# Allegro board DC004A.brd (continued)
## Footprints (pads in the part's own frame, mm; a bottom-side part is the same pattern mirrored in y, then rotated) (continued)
DBV5
  rect 1.27x0.508 smd: 1(-1.1,0.95) 2(-1.1,0) 3(-1.1,-0.95) 4(1.1,-0.95) 5(1.1,0.95)
DIODE_MBRB2515L
  rect 3.048x1.016 smd: 1(5.652,-2.54) 3(5.652,2.54)
  round 0.013 smd: 2(5.652,0)
  rect 8.382x10.668 smd: 4(-5.652,0)
DIODE_SM_1N4148W
  rect 0.889x0.94 smd: 1(-1.575,0) 2(1.575,0)
DUAL_FLATPACK_TPS7H1101-SP
  rect 1.422x0.551 smd: 1(-7.303,4.445) 2(-7.303,3.175) 3(-7.303,1.905) 4(-7.303,0.635) 5(-7.303,-0.635) 6(-7.303,-1.905) 7(-7.303,-3.175) 8(-7.303,-4.445) 9(7.303,-4.445) 10(7.303,-3.175) 11(7.303,-1.905) 12(7.303,-0.635) 13(7.303,0.635) 14(7.303,1.905) 15(7.303,3.175) 16(7.303,4.445)
  rect 6.223x8.89 smd: 17(0,0)
HDR_THVT_1X2_100_M
  rect 1.473x1.473 hole 0.965: 1(0,0)
  round 1.473 hole 0.965: 2(0,-2.54)
HDR_THVT_1X3_100_M
  rect 1.575x1.575 hole 1.016: 1(0,0)
  round 1.575 hole 1.016: 2(0,-2.54) 3(0,-5.08)
HDR_THVT_1X4_100_M
  rect 1.473x1.473 hole 0.965: 1(0,0)
  round 1.473 hole 0.965: 2(0,-2.54) 3(0,-5.08) 4(0,-7.62)
HDR_THVT_2X4_100_M
  rect 1.473x1.473 hole 0.965: 1(0,0)
  round 1.473 hole 0.965: 2(2.54,0) 3(0,-2.54) 4(2.54,-2.54) 5(0,-5.08) 6(2.54,-5.08) 7(0,-7.62) 8(2.54,-7.62)
IND_0603
  rect 0.635x1.016 smd: 1(-0.635,0) 2(0.635,0)
IND_SM_6P7MMX6P7MM
  rect 2.5x2.4 smd: 1(-3.1,0) 2(3.1,0)
JUMPER_SMD_3POS_0402
  rect 0.508x0.508 smd: 1(1.016,0) 2(0,0) 3(-1.016,0)
JUMPER_SMD_3POS_0805
  rect 1.3x1.3 smd: 1(-2.032,0) 2(0,0) 3(2.032,0)
LED_0805
  rect 1.422x1.524 smd: 1(-1.143,0) 2(1.143,0)
MFG125_PLATED
  round 3.556 hole 3.175: 1(0,0)
MSOP_8_118X118_0P65MM
  rect 1.45x0.46 smd: 1(-2.2,0.975) 2(-2.2,0.325) 3(-2.2,-0.325) 4(-2.2,-0.975) 5(2.2,-0.975) 6(2.2,-0.325) 7(2.2,0.325) 8(2.2,0.975)
PROBE_POINT_30PAD
  round 0.762 smd: 1(0,0)
QFN40_RTA_RTB_RHA
  custom 0.076x0.076 smd: 1(-3.025,2.25) 2(-3.025,1.75) 3(-3.025,1.25) 4(-3.025,0.75) 5(-3.025,0.25) 6(-3.025,-0.25) 7(-3.025,-0.75) 8(-3.025,-1.25) 9(-3.025,-1.75) 10(-3.025,-2.25) 11(-2.25,-3.025) 12(-1.75,-3.025) 13(-1.25,-3.025) 14(-0.75,-3.025) 15(-0.25,-3.025) 16(0.25,-3.025) 17(0.75,-3.025) 18(1.25,-3.025) 19(1.75,-3.025) 20(2.25,-3.025) 21(3.025,-2.25) 22(3.025,-1.75) 23(3.025,-1.25) 24(3.025,-0.75) 25(3.025,-0.25) 26(3.025,0.25) 27(3.025,0.75) 28(3.025,1.25) 29(3.025,1.75) 30(3.025,2.25) 31(2.25,3.025) 32(1.75,3.025) 33(1.25,3.025) 34(0.75,3.025) 35(0.25,3.025) 36(-0.25,3.025) 37(-0.75,3.025) 38(-1.25,3.025) 39(-1.75,3.025) 40(-2.25,3.025)
  rect 4.572x4.572 smd: 41(0,0)
QFN_10_83X83_RUN
  rect 0.95x0.28 smd: 1(-0.895,0.75) 2(-0.895,0.25) 3(-0.895,-0.25) 4(-0.895,-0.75) 6(0.895,-0.75) 7(0.895,-0.25) 8(0.895,0.25) 9(0.895,0.75)
  rect 0.28x0.95 smd: 5(0,-0.895) 10(0,0.895)
QFN_64_0P50MM_RGC_FT2232HQ
  custom 0.076x0.076 smd: 1(-4.58,3.753) 2(-4.58,3.252) 3(-4.58,2.752) 4(-4.58,2.252) 5(-4.58,1.751) 6(-4.58,1.251) 7(-4.58,0.751) 8(-4.58,0.25) 9(-4.58,-0.25) 10(-4.58,-0.751) 11(-4.58,-1.251) 12(-4.58,-1.751) 13(-4.58,-2.252) 14(-4.58,-2.752) 15(-4.58,-3.252) 16(-4.58,-3.753) 17(-3.753,-4.58) 18(-3.252,-4.58) 19(-2.752,-4.58) 20(-2.252,-4.58) 21(-1.751,-4.58) 22(-1.251,-4.58) 23(-0.751,-4.58) 24(-0.25,-4.58) 25(0.25,-4.58) 26(0.751,-4.58) 27(1.251,-4.58) 28(1.751,-4.58) 29(2.252,-4.58) 30(2.752,-4.58) 31(3.252,-4.58) 32(3.753,-4.58) 33(4.58,-3.753) 34(4.58,-3.252) 35(4.58,-2.752) 36(4.58,-2.252) 37(4.58,-1.751) 38(4.58,-1.251) 39(4.58,-0.751) 40(4.58,-0.25) 41(4.58,0.25) 42(4.58,0.751) 43(4.58,1.251) 44(4.58,1.751) 45(4.58,2.252) 46(4.58,2.752) 47(4.58,3.252) 48(4.58,3.753) 49(3.753,4.58) 50(3.252,4.58) 51(2.752,4.58) 52(2.252,4.58) 53(1.751,4.58) 54(1.251,4.58) 55(0.751,4.58) 56(0.25,4.58) 57(-0.25,4.58) 58(-0.751,4.58) 59(-1.251,4.58) 60(-1.751,4.58) 61(-2.252,4.58) 62(-2.752,4.58) 63(-3.252,4.58) 64(-3.753,4.58)
  rect 4.318x4.318 smd: 65(0,0)
SJP2_JUMPER_0402
  rect 0.762x1.27 smd: 1(-0.521,0) 2(0.521,0)
SMA_SMEL_373X312
  rect 0.635x5.08 smd: 1(0,-2.54)
  rect 2.286x5.08 smd: 2(-4.445,-2.54) 3(4.445,-2.54) 4(-4.445,-2.54) 5(4.445,-2.54)
SMA_THVT_312X312
  round 2.337 hole 1.575: 1(0,0)
  round 2.464 hole 1.702: 2(-2.54,2.54) 3(2.54,2.54) 4(2.54,-2.54) 5(-2.54,-2.54)
SMA_THVT_SMT_250X250
  round 0.787 smd: 1(0,0)
  round 1.829 hole 1.499: 2(-2.54,-2.54) 3(2.54,-2.54) 4(2.54,2.54) 5(-2.54,2.54)
SMD_JUMPER_L_0402
  rect 0.508x0.508 smd: 1(-0.508,0) 2(0.508,0) 3(0.508,1.016)
SMP_B120
  rect 0.508x1.321 smd: 1(0,-3.1)
  custom 1.3x1.3 smd: 2(0,0)
SO_8_207X207_50
  rect 1.702x0.66 smd: 1(-3.645,1.905) 2(-3.645,0.635) 3(-3.645,-0.635) 4(-3.645,-1.905) 5(3.645,-1.905) 6(3.645,-0.635) 7(3.645,0.635) 8(3.645,1.905)
SOIC_8_197X157_50
  rect 2.159x0.61 smd: 1(-2.44,1.905) 2(-2.44,0.635) 3(-2.44,-0.635) 4(-2.44,-1.905) 5(2.44,-1.905) 6(2.44,-0.635) 7(2.44,0.635) 8(2.44,1.905)
SON_Q5B_8
  rect 1.372x0.711 smd: 1(-2.767,1.905) 2(-2.767,0.635) 3(-2.767,-0.635) 4(-2.767,-1.905) 5(2.767,-1.905) 6(2.767,-0.635) 7(2.767,0.635) 8(2.767,1.905)
SOT_5_120X69_37
  rect 0.61x1.524 smd: 1(-0.95,-1.75) 2(0,-1.75) 3(0.95,-1.75) 4(0.95,1.75) 5(-0.95,1.75)
SOT_5_120X69_57
  rect 0.61x1.524 smd: 1(-0.95,-1.35) 2(0,-1.35) 3(0.95,-1.35) 4(0.95,1.35) 5(-0.95,1.35)
TANT_B
  rect 2.032x2.286 smd: 1(-1.524,0) 2(1.524,0)
TANT_D
  rect 2.108x2.591 smd: 1(-2.896,0) 2(2.896,0)
TANT_X
  rect 2.108x2.591 smd: 1(-2.896,0) 2(2.896,0)
TFMR_5_150X150_50
  rect 1.651x0.762 smd: 1(1.587,1.27) 2(1.587,0) 3(1.587,-1.27) 4(-1.587,-1.27) 6(-1.587,1.27)
TP_THVT_100_RND
  round 2.54 hole 1.016: 1(0,0)
TP_THVT_125_RND_063D
  round 2.362 hole 1.6: 1(0,0)
TSSOP_16_201X177_26
  rect 1.6x0.35 smd: 1(-2.825,2.275) 2(-2.825,1.625) 3(-2.825,0.975) 4(-2.825,0.325) 5(-2.825,-0.325) 6(-2.825,-0.975) 7(-2.825,-1.625) 8(-2.825,-2.275) 9(2.825,-2.275) 10(2.825,-1.625) 11(2.825,-0.975) 12(2.825,-0.325) 13(2.825,0.325) 14(2.825,0.975) 15(2.825,1.625) 16(2.825,2.275)
unnamed
  round 1.016 smd: 1(0,0)
unnamed#3
  round 0.762 smd: (0,0)
VCXO_6_CUSTOM
  rect 5.74x1.956 smd: 1(-3.81,2.54) 2(-3.81,0) 3(-3.81,-2.54) 4(3.81,-2.54) 5(3.81,0) 6(3.81,2.54)
WQFN_64_360X360_0P5MM_PWRPAD
  rect 0.61x0.254 smd: 1(-4.395,3.753) 2(-4.395,3.252) 3(-4.395,2.752) 4(-4.395,2.252) 5(-4.395,1.751) 6(-4.395,1.251) 7(-4.395,0.751) 8(-4.395,0.25) 9(-4.395,-0.25) 10(-4.395,-0.751) 11(-4.395,-1.251) 12(-4.395,-1.751) 13(-4.395,-2.252) 14(-4.395,-2.752) 15(-4.395,-3.252) 16(-4.395,-3.753) 33(4.395,-3.753) 34(4.395,-3.252) 35(4.395,-2.752) 36(4.395,-2.252) 37(4.395,-1.751) 38(4.395,-1.251) 39(4.395,-0.751) 40(4.395,-0.25) 41(4.395,0.25) 42(4.395,0.751) 43(4.395,1.251) 44(4.395,1.751) 45(4.395,2.252) 46(4.395,2.752) 47(4.395,3.252) 48(4.395,3.753)
  rect 0.254x0.61 smd: 17(-3.753,-4.395) 18(-3.252,-4.395) 19(-2.752,-4.395) 20(-2.252,-4.395) 21(-1.751,-4.395) 22(-1.251,-4.395) 23(-0.751,-4.395) 24(-0.25,-4.395) 25(0.25,-4.395) 26(0.751,-4.395) 27(1.251,-4.395) 28(1.751,-4.395) 29(2.252,-4.395) 30(2.752,-4.395) 31(3.252,-4.395) 32(3.753,-4.395) 49(3.753,4.395) 50(3.252,4.395) 51(2.752,4.395) 52(2.252,4.395) 53(1.751,4.395) 54(1.251,4.395) 55(0.751,4.395) 56(0.25,4.395) 57(-0.25,4.395) 58(-0.751,4.395) 59(-1.251,4.395) 60(-1.751,4.395) 61(-2.252,4.395) 62(-2.752,4.395) 63(-3.252,4.395) 64(-3.753,4.395)
  rect 7.188x7.188 smd: 65(0,0)
XTAL_2_SM_126X197
  rect 1.9x2.4 smd: 1(-2.05,0) 2(2.05,0)

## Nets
1.538V: C227.1 C232.1 C254.1 C270.1 FB25.1 L6.2 PP11.1 R191.2
3.3VCLK: C261.1 C262.1 C263.1 FB20.1 FB21.1 R198.1 U16.6(OUT1) U16.7(OUT2) U16.8(OUT3)
3.3VLMX: C266.1 C267.1 C268.1 FB22.1 FB23.1 R200.1 U17.6(OUT1) U17.7(OUT2) U17.8(OUT3)
5.0V_IN: D13.4 F1.1 J37.1 Q3.5(D5) Q3.6(D6) Q3.7(D7) Q3.8(D8) TP12.1(TP) U13.5(VIN)
5VIN: C196.1 C198.1 C213.1 C214.1 C255.1 C256.1 C259.1 C260.1 C264.1 C265.1 F1.2 Q3.1(S1) Q3.2(S2) Q3.3(S3) R148.1 R190.1 R193.1 R210.1 R212.1 U14.5(VIN) U14.6(PVIN#6) U14.7(PVIN#7) U16.1(\\S\H\D\N\) U16.2(IN1) U16.3(IN2) U16.4(IN3) U17.1(\\S\H\D\N\) U17.2(IN1) U17.3(IN2) U17.4(IN3) U18.5(VIN) U18.6(PVIN#6) U18.7(PVIN#7)
+2.2V: C208.1 C209.1 C212.1 C217.1 FB24.1 L7.2 PP12.1 R211.2
+3.3V_LMX: C100.1 C101.1 C102.2 C103.1 C106.1 C107.2 C113.1 C114.2 C242.1 C243.1 C244.1 C245.1 FB22.2 PP7.1 R46.2 U3.7(VCCDIG) U3.11(VCCCP) U3.15(VCCDIV) U3.21(VCCBUF) U3.26(VCCDBLR) U3.37(VCCVCO)
+3.3V_LMXRF: C99.1 C105.1 C247.1 C248.1 FB23.2 PP8.1 R44.2 R45.2 R48.2 R49.2
+3.3VCLK: C229.1 C230.1 C233.1 C234.1 FB1.2 FB2.1 FB3.1 FB4.1 FB5.1 FB6.1 FB10.1 FB11.1 FB20.2 PP5.1 R82.1 R88.1 R96.2 SJP1.3(PIN3)
GND: C1.2 C2.2 C3.1 C4.1 C14.1 C17.2 C24.1 C41.2 C42.2 C43.2 C54.2 C55.2 C56.2 C57.2 C58.2 C59.2 C60.2 C61.2 C62.2 C63.2 C64.2 C65.2 C66.2 C67.2 C68.2 C69.2 C70.2 C71.2 C72.2 C73.2 C74.2 C75.2 C76.2 C77.2 C78.2 C79.2 C80.2 C81.2 C82.2 C83.2 C84.2 C85.2 C86.2 C87.2 C88.2 C89.2 C90.2 C91.2 C92.2 C93.2 C94.2 C95.2 C96.2 C99.2 C100.2 C101.2 C102.1 C103.2 C104.1 C105.2 C106.2 C107.1 C109.2 C111.1 C112.1 C113.2 C114.1 C115.1 C116.1 C117.1 C118.1 C119.2 C121.2 C122.2 C123.2 C124.2 C125.2 C126.2 C127.2 C129.2 C130.2 C132.2 C137.1 C138.1 C139.1 C140.1 C141.1 C146.1 C152.1 C154.1 C155.1 C156.1 C157.2 C158.2 C159.2 C160.1 C161.1 C162.1 C163.2 C164.2 C165.2 C166.2 C167.1 C168.2 C169.2 C170.2 C171.2 C172.2 C173.2 C174.2 C175.2 C176.2 C177.2 C178.2 C179.2 C180.2 C181.2 C182.2 C183.2 C184.2 C185.2 C186.2 C187.2 C188.2 C189.2 C190.2 C191.2 C192.2 C193.2 C194.2 C195.2 C196.2 C198.2 C200.2 C201.2 C202.2 C203.2 C204.2 C205.2 C206.2 C207.2 C208.2 C209.2 C211.2 C212.2 C213.2 C214.2 C215.2 C216.2 C218.2 C219.2 C220.2 C222.2 C223.2 C224.2 C225.2 C226.2 C227.2 C228.2 C229.2 C230.2 C231.2 C232.2 C233.2 C234.2 C236.2 C237.2 C242.2 C243.2 C244.2 C245.2 C247.2 C248.2 C255.2 C256.2 C258.2 C259.2 C260.2 C262.2 C263.2 C264.2 C265.2 C267.2 C268.2 C269.2 C270.2 C271.2 C272.2 D2.2(CATHODE) D3.2(CATHODE) D4.2(CATHODE) D5.2(CATHODE) D6.2(CATHODE) D8.2(CATHODE) D13.1 D13.3 FB16.2 FB17.2 FB18.2 FB19.2 FB24.2 FB25.2 J1.2(SHIELD1) J2.2(SHIELD1) J2.3(SHIELD2) J2.4(SHIELD3) J2.5(SHIELD4) J3.2(SHIELD1) J4.2(SHIELD1) J5.2(SHIELD1) J5.3(SHIELD2) J5.4(SHIELD3) J5.5(SHIELD4) J6.2(SHIELD1) J14.2(GND#2) J14.3(GND#3) J14.4(GND#4) J14.5(GND#5) J15.2(GND#2) J15.3(GND#3) J15.4(GND#4) J15.5(GND#5) J18.2(GND#2) J18.3(GND#3) J18.4(GND#4) J18.5(GND#5) J20.2(SHIELD1) J22.2(GND#2) J22.3(GND#3) J22.4(GND#4) J22.5(GND#5) J23.2(SHIELD1) J23.3(SHIELD2) J23.4(SHIELD3) J23.5(SHIELD4) J24.2(SHIELD1) J24.3(SHIELD2) J24.4(SHIELD3) J24.5(SHIELD4) J25.A1 J25.A4 J25.A5 J25.A8 J25.A9 J25.A12 J25.A13 J25.A16 J25.A17 J25.A20 J25.A21 J25.A24 J25.A25 J25.A28 J25.A29 J25.A32 J25.A33 J25.A36 J25.A37 J25.A40 J25.B3 J25.B6 J25.B7 J25.B10 J25.B11 J25.B14 J25.B15 J25.B18 J25.B22 J25.B23 J25.B26 J25.B27 J25.B30 J25.B31 J25.B34 J25.B35 J25.B38 J25.B39 J25.C1 J25.C5 J25.C8 J25.C9 J25.C21 J25.C24 J25.C25 J25.C28 J25.C29 J25.C32 J25.C33 J25.C36 J25.C38 J25.C40 J25.D3 J25.D6 J25.D7 J25.D25 J25.D28 J25.D37 J25.D39 J25.E26 J25.E29 J25.E32 J25.E35 J25.E38 J25.E40 J25.F9 J25.F27 J25.F30 J25.F33 J25.F36 J25.F39 J25.G5 J25.G8 J25.G11 J25.G14 J25.G26 J25.G29 J25.G32 J25.G35 J25.G38 J25.G40 J25.H27 J25.H30 J25.H33 J25.H36 J25.H39 J25.J26 J25.J29 J25.J32 J25.J35 J25.J38 J25.J40 J25.K27 J25.K30 J25.K33 J25.K36 J25.K39 J25.L30 J25.L31 J25.L34 J25.L35 J25.L38 J25.L39 J25.M28 J25.M29 J25.M32 J25.M33 J25.M36 J25.M37 J25.M40 J25.Y4 J25.Y5 J25.Y8 J25.Y9 J25.Y12 J25.Y13 J25.Y16 J25.Y17 J25.Y20 J25.Y21 J25.Y24 J25.Y25 J25.Y28 J25.Y29 J25.Y32 J25.Y33 J25.Y36 J25.Y37 J25.Y40 J25.Z2 J25.Z3 J25.Z6 J25.Z7 J25.Z10 J25.Z11 J25.Z14 J25.Z15 J25.Z18 J25.Z19 J25.Z22 J25.Z23 J25.Z26 J25.Z27 J25.Z30 J25.Z31 J25.Z34 J25.Z35 J25.Z38 J25.Z39 J28.3 J31.5(GND) J31.6(GND1) J31.7(GND2) J31.8(GND3) J31.9(GND4) J37.2 J37.3 J38.2(GND#2) J38.3(GND#3) J38.4(GND#4) J38.5(GND#5) JP5.1 MT1.1 MT2.1 R11.2 R12.2 R17.2 R18.2 R21.2 R23.2 R26.2 R31.2 R32.2 R33.2 R51.1 R52.1 R53.1 R56.2 R57.2 R58.2 R61.2 R62.2 R63.2 R64.2 R65.2 R66.2 R68.2 R71.2 R72.2 R74.2 R75.2 R78.2 R79.2 R80.2 R81.2 R84.2 R85.2 R86.2 R87.2 R89.2 R90.2 R92.2 R93.2 R94.2 R95.2 R99.2 R106.2 R108.2 R109.2 R122.1 R184.2 R185.2 R187.2 R188.2 R189.2 R195.2 R196.1 R197.2 R199.2 R202.2 R204.2 R207.2 R213.1 R214.1 R217.2 R219.2 R221.2 SJP1.1(PIN1) SJP2.2 SJP13.2 SJP14.2 T1.2(SECONDARY_CT) T1.4(PRIMARY) T2.4(PRIMARY) TP6.1(TP) TP7.1(TP) TP8.1(TP) TP11.1(TP) TP13.1(TP) TP14.1(TP) U1.A1(AGND#A1) U1.A3(AGND#A3) U1.A6(AGND#A6) U1.A14(DGND#A14) U1.B1(AGND#B1) U1.B3(AGND#B3) U1.B4(AGND#B4) U1.B5(AGND#B5) U1.B6(AGND#B6) U1.B14(DGND#B14) U1.C6(AGND#C6) U1.C7(AGND#C7) U1.C8(DGND#C8) U1.C9(DGND#C9) U1.D4(AGND#D4) U1.D5(AGND#D5) U1.D6(AGND#D6) U1.D7(AGND#D7) U1.D8(DGND#D8) U1.D9(DGND#D9) U1.D10(DGND#D10) U1.D11(DGND#D11) U1.E4(AGND#E4) U1.E5(AGND#E5) U1.E6(AGND#E6) U1.E7(AGND#E7) U1.E8(DGND#E8) U1.E9(DGND#E9) U1.E10(DGND#E10) U1.E11(DGND#E11) U1.F1(AGND#F1) U1.F4(AGND#F4) U1.F5(AGND#F5) U1.F6(AGND#F6) U1.F7(AGND#F7) U1.F8(DGND#F8) U1.F9(DGND#F9) U1.F10(DGND#F10) U1.F11(DGND#F11) U1.G2(AGND#G2) U1.G4(AGND#G4) U1.G5(AGND#G5) U1.G6(AGND#G6) U1.G7(AGND#G7) U1.G8(DGND#G8) U1.G9(DGND#G9) U1.G10(DGND#G10) U1.G11(DGND#G11) U1.H2(AGND#H2) U1.H4(AGND#H4) U1.H5(AGND#H5) U1.H6(AGND#H6) U1.H7(AGND#H7) U1.H8(DGND#H8) U1.H9(DGND#H9) U1.H10(DGND#H10) U1.H11(DGND#H11) U1.J1(AGND#J1) U1.J4(AGND#J4) U1.J5(AGND#J5) U1.J6(AGND#J6) U1.J7(AGND#J7) U1.J8(DGND#J8) U1.J9(DGND#J9) U1.J10(DGND#J10) U1.J11(DGND#J11) U1.K4(AGND#K4) U1.K5(AGND#K5) U1.K6(AGND#K6) U1.K7(AGND#K7) U1.K8(DGND#K8) U1.K9(DGND#K9) U1.K10(DGND#K10) U1.K11(DGND#K11) U1.L4(AGND#L4) U1.L5(AGND#L5) U1.L6(AGND#L6) U1.L7(AGND#L7) U1.L8(DGND#L8) U1.L9(DGND#L9) U1.L10(DGND#L10) U1.L11(DGND#L11) U1.M6(AGND#M6) U1.M7(AGND#M7) U1.M8(DGND#M8) U1.M9(DGND#M9) U1.N1(AGND#N1) U1.N3(AGND#N3) U1.N4(AGND#N4) U1.N5(AGND#N5) U1.N6(AGND#N6) U1.N9(DGND#N9) U1.N14(DGND#N14) U1.P1(AGND#P1) U1.P3(AGND#P3) U1.P6(AGND#P6) U1.P14(DGND#P14) U2.5(A0) U2.6(GND) U3.2(GND#2) U3.4(GND#4) U3.6(GND#6) U3.13(GND#13) U3.14(GND#14) U3.25(GND#25) U3.31(GND#31) U3.34(GND#34) U3.39(GND#39) U3.40(NC4) U3.41(PWRPAD) U4.65(DAP) U5.3(A2) U5.4(VSS) U6.2(GND) U7.3(GND) U8.1(GND#1) U8.5(GND#5) U8.10(AGND) U8.11(GND#11) U8.13(TEST) U8.15(GND#15) U8.25(GND#25) U8.35(GND#35) U8.47(GND#47) U8.51(GND#51) U8.65(PWRPAD) U9.5(VSS) U10.7(DIR3) U10.10(GND) U11.10(GND) U12.1(DIR1) U12.2(DIR2) U12.7(DIR3) U12.8(DIR4) U12.10(GND) U13.2(GND) U14.1(GND) U14.8(PGND#8) U14.9(PGND#9) U14.10(PGND#10) U14.21(PWRPAD) U15.4(V-) U16.10(GND) U16.11(PWRPAD) U17.10(GND) U17.11(PWRPAD) U18.1(GND) U18.8(PGND#8) U18.9(PGND#9) U18.10(PGND#10) U18.21(PWRPAD) U19.8(GND) U19.17(PWRPAD) U20.8(GND) U20.17(PWRPAD) Y1.3(GND)
VBUS: C175.1 R111.1 U6.1(IN) U6.3(EN)
VBUSS: C173.1 FB14.1 U6.5(OUT)
VCCIN: C104.2 U3.10(VCCIN)
VDDD33: C1.1 C2.1 C41.1 C42.1 C43.1 C172.1 C180.1 C186.1 C187.1 C188.1 C189.1 C190.1 C192.1 C194.1 C236.1 C237.1 D1.1(ANODE) D7.1(ANODE) FB12.1 FB13.1 FB21.2 JP6.1(PIN1) PP6.1 R27.1 R28.1 R30.1 R39.1 R41.1 R114.1 R115.1 R123.1 R124.1 R125.1 R130.1 U2.1(V+) U2.10(A1) U7.5(VCC) U8.20(VCCIO#20) U8.31(VCCIO#31) U8.42(VCCIO#42) U8.56(VCCIO#56) U9.8(VCC) U10.1(DIR1) U10.2(DIR2) U10.8(DIR4) U10.16(VCCA) U11.1(DIR1) U11.2(DIR2) U11.7(DIR3) U11.8(DIR4) U11.16(VCCA) U12.16(VCCA) U15.8(V+)
VDDL19: C191.1 C193.1 C195.1 C200.1 C201.1 FB16.3 PP13.1 R132.1 U10.15(VCCB) U11.15(VCCB) U12.15(VCCB)
VINA: BALUN1.1(IN) J2.1(CENTER)
VINB: BALUN2.1(IN) J5.1(CENTER)
1P8V_USB: C178.1 C179.1 C181.1 C182.1 C183.1 PP16.1 U8.12(VCORE#12) U8.37(VCORE#37) U8.49(VREGOUT) U8.64(VCORE#64)
2: D13.2
3P3USB: C170.1 C171.1 FB13.2 PP15.1 U8.9(VPLL)
3P3V_RX: PP18.1 R105.2
3P3VAUX: C167.2 J25.D32 J28.4 U5.8(VCC)
12P0V_RX: J25.C35 J25.C37
ADBUS0: SJP3.3(PIN3) U8.16(ADBUS0)
ADBUS1: SJP4.3(PIN3) U8.17(ADBUS1)
ADBUS2: SJP5.3(PIN3) U8.18(ADBUS2)
ADBUS3: SJP6.3(PIN3) U8.19(ADBUS3)
ADC_CLK: PP1.1 R133.2 U1.G14(SCLK)
ADC_SCSB: PP4.1 R136.2 U1.G13(\\S\C\S\)
ADC_SDI: PP2.1 R134.2 U1.H13(SDI)
ADC_SDO: PP3.1 R135.2 U1.H14(SDO)
BDBUS0: R112.1 U8.26(BDBUS0)
BDBUS1: U7.2(A) U8.27(BDBUS1)
BDBUS2: R113.1 U8.28(BDBUS2)
BDBUS3: U7.1(O\E\) U8.29(BDBUS3)
CALTRG: J9.2 R23.1 U1.A9(CALTRG)
CDBUS0: R118.1 U8.38(CDBUS0)
CDBUS1: R119.1 U8.39(CDBUS1)
CDBUS2: R115.2 R120.1 U8.40(CDBUS2)
CDBUS3: R114.2 R121.1 U8.41(CDBUS3)
CE: JP5.2 R46.1 U3.1(CE)
CLK+: C49.1 R43.2 T2.1(SECONDARY_DOT)
CLK-: C52.1 R43.1 T2.3(SECONDARY)
CLK-IN: R67.1 R69.1 R70.2 R72.1 T1.6(PRIMARY_DOT)
CLK_+: C48.2 C49.2 C50.2 U1.G1(CLK+)
CLK_-: C51.2 C52.2 C53.2 U1.H1(CLK-)
CLKIN0: J38.1(CENTER) R186.1 R187.1
CLKIN0_N: C24.2 U4.38(CLKIN0N)
CLKIN0_P: C20.2 U4.37(CLKIN0P)
CLKIN1: C20.1 R186.2
CLKIN1_N: C136.2 C137.2 U4.35(CLKIN1N/FBCLKINN/FINN)
CLKIN1_P: C134.2 U4.34(CLKIN1P/FBCLKINP/FINP)
CLKINN: C136.1 R73.2 T1.3(SECONDARY)
CLKINP: C134.1 R68.1 R69.2 R73.1 T1.1(SECONDARY_DOT)
CLKLA_0N: R90.1 R127.1 U4.63(DCLKOUT12N)
CLKLA_0P: R89.1 R126.1 U4.62(DCLKOUT12P)
CLKM: C48.1 C135.2
CLKP: C53.1 C133.2
CP1: C128.1 C130.1 U4.32(CPOUT1) Y1.1(VC)
CP2: C131.1 C132.1 U4.46(CPOUT2)
CPOUT: C119.1 C120.1 R54.1 U3.12(CPOUT)
DA0+: C5.1 U1.E14(DA0+)
DA0-: C6.1 U1.F14(DA0-)
DA0_M: C6.2 J25.A11
DA0_P: C5.2 J25.A10
DA1+: C7.1 U1.C14(DA1+)
DA1-: C8.1 U1.D14(DA1-)
DA1_M: C8.2 J25.C7
DA1_P: C7.2 J25.C6
DA2+: C9.1 U1.A12(DA2+)
DA2-: C10.1 U1.A13(DA2-)
DA2_M: C10.2 J25.A7
DA2_P: C9.2 J25.A6
DA3+: C11.1 U1.A10(DA3+)
DA3-: C12.1 U1.A11(DA3-)
DA3_M: C12.2 J25.A3
DA3_P: C11.2 J25.A2
DA4+: C13.1 U1.E13(DA4+)
DA4-: C15.1 U1.F13(DA4-)
DA4_M: C15.2 J25.Y15
DA4_P: C13.2 J25.Y14
DA5+: C16.1 U1.C13(DA5+)
DA5-: C18.1 U1.D13(DA5-)
DA5_M: C18.2 J25.Y11
DA5_P: C16.2 J25.Y10
DA6+: C19.1 U1.B12(DA6+)
DA6-: C21.1 U1.B13(DA6-)
DA6_M: C21.2 J25.B9
DA6_P: C19.2 J25.B8
DA7+: C22.1 U1.B10(DA7+)
DA7-: C23.1 U1.B11(DA7-)
DA7_M: C23.2 J25.B5
DA7_P: C22.2 J25.B4
DB0+: C25.1 U1.K14(DB0+)
DB0-: C26.1 U1.J14(DB0-)
DB0_M: C26.2 J25.B12
DB0_P: C25.2 J25.B13
DB1+: C27.1 U1.M14(DB1+)
DB1-: C28.1 U1.L14(DB1-)
DB1_M: C28.2 J25.A14
DB1_P: C27.2 J25.A15
DB2+: C29.1 U1.P12(DB2+)
DB2-: C30.1 U1.P13(DB2-)
DB2_M: C30.2 J25.B16
DB2_P: C29.2 J25.B17
DB3+: C31.1 U1.P10(DB3+)
DB3-: C32.1 U1.P11(DB3-)
DB3_M: C32.2 J25.A18
DB3_P: C31.2 J25.A19
DB4+: C33.1 U1.K13(DB4+)
DB4-: C34.1 U1.J13(DB4-)
DB4_M: C34.2 J25.Z12
DB4_P: C33.2 J25.Z13
DB5+: C35.1 U1.M13(DB5+)
DB5-: C36.1 U1.L13(DB5-)
DB5_M: C36.2 J25.Z16
DB5_P: C35.2 J25.Z17
DB6+: C37.1 U1.N12(DB6+)
DB6-: C38.1 U1.N13(DB6-)
DB6_M: C38.2 J25.Y18
DB6_P: C37.2 J25.Y19
DB7+: C39.1 U1.N10(DB7+)
DB7-: C40.1 U1.N11(DB7-)
DB7_M: C40.2 J25.Y22
DB7_P: C39.2 J25.Y23
DCLKOUT2_N: C135.1 R75.1 U4.16(DCLKOUT2N)
DCLKOUT2_P: C133.1 R74.1 U4.15(DCLKOUT2P)
DCLKOUT6_N: C153.1 R95.1 U4.28(DCLKOUT6N)
DCLKOUT6_P: C151.1 R94.1 U4.27(DCLKOUT6P)
DCLKOUT8_N: R24.1 R57.1 U4.52(DCLKOUT8N)
DCLKOUT8_P: R22.1 R58.1 U4.51(DCLKOUT8P)
DCLKOUT10_N: C143.2 J24.1(CENTER)
DCLKOUT10_P: C142.2 J23.1(CENTER)
DCLKOUT10N: C143.1 R87.1 U4.55(DCLKOUT10N)
DCLKOUT10P: C142.1 R86.1 U4.54(DCLKOUT10P)
DDBUS0: U8.48(DDBUS0) U11.3(A1)
DDBUS1: U8.52(DDBUS1) U11.4(A2)
DDBUS2: U8.53(DDBUS2) U11.5(A3)
DDBUS3: U8.54(DDBUS3) U11.6(A4)
DDBUS4: R225.2 U8.55(DDBUS4) U12.3(A1)
DDBUS5: U8.57(DDBUS5) U12.4(A2)
DDBUS6: R226.2 U8.58(DDBUS6) U12.5(A3)
DDBUS7: U8.59(DDBUS7) U12.6(A4)
DEVCLKIN: J18.1(CENTER) T2.6(PRIMARY_DOT)
DM: R116.2 U8.7(DM)
DP: R117.2 U8.8(DP)
EE_ADDR0_RX: J25.C34 U5.1(A0)
EE_ADDR1_RX: J25.D35 U5.2(A1)
EECLK: R124.2 U8.62(EECLK) U9.2(CLK)
EECS: R125.2 U8.63(EECS) U9.1(CS)
EEDATA: R131.1 U8.61(EEDATA) U9.3(DI)
FMC_ADC_SCSB: J25.H38 SJP6.1(PIN1)
FMC_ADC_SDI: J25.G36 SJP5.1(PIN1)
FMC_DATA: J25.G37 SJP4.1(PIN1) SJP8.1(PIN1)
FMC_LMK_SCSB: J25.G34 SJP9.1(PIN1)
FMC_LMK_SDI: J25.G24 SJP12.1(PIN1)
FMC_LMX_SCSB: J25.G33 SJP10.1(PIN1)
FMC_LMX_SDI: J25.G21 SJP11.1(PIN1)
FMC_SCL: J25.C30 J28.2 U5.6(SCL)
FMC_SCLK: J25.H37 SJP3.1(PIN1) SJP7.1(PIN1)
FMC_SDA: J25.C31 J28.1 U5.5(SDA)
FPGA_JESD_CLK_A_N: J25.D5 R129.2
FPGA_JESD_CLK_A_P: J25.D4 R128.2
FPGA_JESD_CLK_B_N: J25.G7 R127.2
FPGA_JESD_CLK_B_P: J25.G6 R126.2
FPGA_JESD_CLK_C_N: J25.Z21 R24.2
FPGA_JESD_CLK_C_P: J25.Z20 R22.2
FPGA_JESD_SYSREFM: J25.G10 R60.2
FPGA_JESD_SYSREFP: J25.G9 R59.2
GTXCLKM: R64.1 R129.1 U4.2(DCLKOUT0N)
GTXCLKP: R65.1 R128.1 U4.1(DCLKOUT0P)
HSPC_PRSNT_M2C_L: J25.Z1 J30.1
INA+: BALUN1.3(O1) R1.1
INA-: BALUN1.2(O2) R4.1
INA_+: J1.1(CENTER) R180.1
INA_-: J3.1(CENTER) R179.1
INAN: R4.2 R179.2 U1.A5(INA-)
INAP: R1.2 R180.2 U1.A4(INA+)
INB+: BALUN2.2(O2) R6.1
INB-: BALUN2.3(O1) R9.1
INB_+: J4.1(CENTER) R151.1
INB_-: J6.1(CENTER) R162.1
INBN: R9.2 R162.2 U1.P5(INB-)
INBP: R6.2 R151.2 U1.P4(INB+)
JESD_SYSREFM: R60.1 R61.1 U4.4(SDCLKOUT1N)
JESD_SYSREFP: R59.1 R62.1 U4.3(SDCLKOUT1P)
LMK04828_CSB: SJP9.2(PIN2) TP5.1(TP) U4.18(\\C\S\)
LMK04828_SYNC: J25.J15 R97.2
LMK LOCKED: D5.1(ANODE) R102.1
LMK_CLKIN: J22.1(CENTER) R70.1 R71.1
LMK_LMX_CLK: SJP7.2(PIN2) U3.16(SCK) U4.19(SCK)
LMK_LMX_DATA: SJP8.2(PIN2) U3.17(SDI) U4.20(SDIO)
LMK_SDO: R99.1 SJP12.2(PIN2) U4.5(RESET)
LMX_CLKB: C108.2 R52.2 R67.2
LMX_CLKM: C50.1 R45.1 U3.22(RFOUTAM)
LMX_CLKP: C51.1 R44.1 U3.23(RFOUTAP)
LMX_CSB: SJP10.2(PIN2) U3.24(CSB)
LMX_OSCM: C151.2 C249.1 U3.9(OSCINM)
LMX_OSCP: C153.2 C250.1 U3.8(OSCINP)
LMX_SDO: R47.2 SJP11.2(PIN2)
MASTER_BYPASS: C124.1 C125.1 C126.1 FB24.3 SJP15.2(PIN2)
MASTER_BYPASS1: SJP15.1(PIN1) SJP16.3(PIN3)
MUX_OUT: R47.1 R50.2 U3.20(MUXOUT)
NCOA0: J7.2 R11.1 R138.2 U1.A7(NCOA0)
NCOA1: J7.4 R12.1 R139.2 U1.B7(NCOA1)
NCOB0: J7.6 R17.1 R140.2 U1.P7(NCOB0)
NCOB1: J7.8 R18.1 R141.2 U1.N7(NCOB1)
OSC_M: C250.2 R188.1 U4.41(OSCOUTN)
OSC_P: C249.2 R189.1 U4.40(OSCOUTP)
OSCI: C184.1 U8.2(OSCI) Y2.2
OSCINN: C150.2 C152.2 U4.44(OSCINN)
OSCINP: C145.2 C146.2 U4.43(OSCINP)
OSCN: C149.2 C150.1 R88.2 R93.1
OSCO: C185.1 U8.3(OSCO) Y2.1
OSCP: C144.2 C145.1 R82.2 R85.1
OVRA: J25.H28 R225.1
OVRA0: D12.1(ANODE) J25.G27 R143.2 U1.A8(OVRA0)
OVRA1: R144.2 U1.B8(OVRA1)
OVRB: J25.H29 R226.1
OVRB0: D9.1(ANODE) J25.D26 R145.2 U1.P8(OVRB0)
OVRB1: R146.2 U1.N8(OVRB1)
PD: J8.2 R21.1 U1.P9(PD)
PG_RX1: J25.F1 J26.2 R104.2
PG_U14: R210.2 R223.1 U14.20(PWRGD)
PLL2 LOCKED: D6.1(ANODE) R103.1
PRSNT_M2C_L: J25.H2 R106.1
RFOUTB_M: C110.1 R49.1 U3.19(RFOUTBM)
RFOUTB_P: C108.1 R48.1 U3.18(RFOUTBP)
RFOUTBM: C110.2 J20.1(CENTER) R53.2
SLAVE_BYPASS: C17.1 C123.1 C129.1 FB25.3 SJP17.2(PIN2)
SLAVE_BYPASS1: FB18.1 FB19.1 R222.2 SJP17.1(PIN1)
STAT 0: D3.1(ANODE) R100.1
STAT 1: D4.1(ANODE) R101.1
SYNC: R96.1 R97.1 R98.1 TP4.1(TP) U4.6(SYNC)
SYNC_N: J25.G13 R36.1
SYNC_P: J25.G12 R35.1
SYNC_SE: J25.H31 R25.1 R98.2
SYNC_SW: R224.2 U14.4(SYNC)
SYNCSE: R25.2 R26.1 U1.B2(SYNC~_SE)
SYS+: C45.2 U1.L1(SYSREF+)
SYS-: C47.2 U1.M1(SYSREF-)
SYSREF+: R76.1 R78.1 U4.13(SDCLKOUT3P)
SYSREF-: R77.1 R79.1 U4.14(SDCLKOUT3N)
SYSREFM: C47.1 R77.2 R80.1
SYSREFP: C45.1 R76.2 R81.1
TCRIT1: R28.2 R37.2 TP1.1(TP) U2.4(\\T\H\E\R\M\)
TCRIT2: R27.2 TP2.1(TP) U2.7(\\A\L\E\R\T\/\T\H\E\R\M\2\)
TDI: J25.D30 J27.1
TDIODE+: J17.2 R40.2 U1.N2(TDIODE+)
TDIODE-: J17.1 R42.2 U1.P2(TDIODE-)
TDIODEN: C44.2 R42.1 U2.3(D-)
TDIODEP: C44.1 R40.1 U2.2(D+)
TDO: J25.D31 J27.2
TMP461_SMBCLK: R41.2 R112.2 U2.9(SCL)
TMP461_SMBDAT: R39.2 R110.2 R113.2 U2.8(SDA)
TMSP+: J14.1(CENTER) R34.1
TMSP-: J15.1(CENTER) R38.1
TMSTP+: R34.2 R35.2 U1.C1(TMSTP+)
TMSTP-: R36.2 R38.2 U1.D1(TMSTP-)
V_BUS: C174.1 C177.1 FB14.2 JP6.3(PIN3)
VA11: C54.1 C55.1 C56.1 C57.1 C58.1 C59.1 C60.1 C61.1 C62.1 C63.1 C66.1 C67.1 C68.1 C218.1 C219.1 C220.1 FB18.3 PP9.1 PP19.1 U1.D3(VA11#D3) U1.E3(VA11#E3) U1.F2(VA11#F2) U1.F3(VA11#F3) U1.G3(VA11#G3) U1.H3(VA11#H3) U1.J2(VA11#J2) U1.J3(VA11#J3) U1.K3(VA11#K3) U1.L3(VA11#L3)
VA19: C69.1 C70.1 C71.1 C72.1 C73.1 C74.1 C75.1 C76.1 C77.1 C78.1 C79.1 C80.1 C81.1 C82.1 C83.1 C202.1 C203.1 C204.1 C205.1 FB17.3 PP14.1 PP20.1 R13.1 R14.1 R15.1 R16.1 R19.1 R20.1 U1.C2(VA19#C2) U1.C3(VA19#C3) U1.C4(VA19#C4) U1.C5(VA19#C5) U1.D2(VA19#D2) U1.E1(VA19#E1) U1.E2(VA19#E2) U1.K1(VA19#K1) U1.K2(VA19#K2) U1.L2(VA19#L2) U1.M2(VA19#M2) U1.M3(VA19#M3) U1.M4(VA19#M4) U1.M5(VA19#M5)
VADJ_RX: J25.E39 J25.F40 J25.G39 J25.H40 PP17.1 R104.1 R107.1
VBIAS_VCO: C116.2 U3.3(VBIASVCO)
VBIASBANK: C109.1 C111.2 U3.27(VBIASBANK)
VD11: C64.1 C65.1 C84.1 C85.1 C86.1 C87.1 C88.1 C89.1 C90.1 C91.1 C92.1 C93.1 C94.1 C95.1 C96.1 C222.1 C223.1 C224.1 FB19.3 PP10.1 PP21.1 U1.C10(VD11#C10) U1.C11(VD11#C11) U1.C12(VD11#C12) U1.D12(VD11#D12) U1.E12(VD11#E12) U1.F12(VD11#F12) U1.G12(VD11#G12) U1.H12(VD11#H12) U1.J12(VD11#J12) U1.K12(VD11#K12) U1.L12(VD11#L12) U1.M10(VD11#M10) U1.M11(VD11#M11) U1.M12(VD11#M12)
VIO_B_M2C_RX: J25.J39 J25.K40 R107.2
VPHY: C168.1 C169.1 FB12.2 U8.4(VPHY)
VREF_VCO1: C112.2 U3.29(VREFVCO#29)
VREF_VCO2: C115.2 U3.36(VREFVCO#36)
VREG_VCO: C117.2 U3.38(VREGVCO)
VREGIN: C176.1 JP6.2(PIN2) U8.50(VREGIN)
VTUNE: C122.1 R55.2 U3.35(VTUNE)
Y1_N: R91.1 R92.1 Y1.4(OUT_N)
Y1_P: R83.1 R84.1 Y1.5(OUT_P)
YO1_N: C149.1 R91.2
YO1_P: C144.1 R83.2
N18340257: D8.1(ANODE) R148.2
N19884870: C138.2 C139.2 C140.2 C141.2 FB1.1 Y1.6(VDD)
N19884947: SJP1.2(PIN2) Y1.2(NC)
N19887754: FB8.2 U4.42(VCC8_OSCIN)
N19887756: C160.2 C161.2 C162.2 FB6.2 FB7.1 FB8.1 FB9.1 U4.47(VCC10_PLL2)
N19887760: C165.1 FB10.2 U4.53(VCC11_CG3)
N19887762: C166.1 FB11.2 U4.64(VCC12_CG0)
N19887789: R102.2 U4.31(STATUS_LD1)
N19887795: R103.2 U4.48(STATUS_LD2)
N19887804: R101.2 U4.59(CLKIN_SEL1)
N19887822: R100.2 U4.58(CLKIN_SEL0)
N19887828: C163.1 U4.12(LDOBYP2)
N19887830: C164.1 U4.11(LDOBYP1)
N19887836: C154.2 C155.2 C156.2 FB2.2 U4.10(VCC1_VCO) U4.33(VCC5_DIG) U4.36(VCC6_PLL1)
N19887876: FB7.2 U4.39(VCC7_OSCOUT)
N19887878: FB9.2 U4.45(VCC9_CP2)
N19887910: C158.1 FB4.2 U4.21(VCC3_SYSREF)
N19887912: C157.1 FB3.2 U4.17(VCC2_CG1)
N19887930: C159.1 FB5.2 U4.26(VCC4_CG2)
N19955835: Q3.4(G) U13.4(GATE)
N20234062: C118.2 U3.33(VBIASVARAC)
N20239082: R51.2 U3.30(REXT)
N20251064: C120.2 R56.1
N20251377: C121.1 R54.2 R55.1
N20258125: D2.1(ANODE) R50.1
N20381922: R130.2 U8.14(RESET)
N20381931: R122.2 U8.6(REF)
N20382558: R123.2 R131.2 U9.4(DO)
N20382827: J31.3(D+) R117.1
N20382847: J31.2(D-) R116.1
N20392160: J31.1(VBUS) R111.2
N20393078: D7.2(CATHODE) R109.1
N20442573: J7.1 R13.2
N20442576: J7.3 R14.2
N20442579: J7.5 R15.2
N20442582: J7.7 R16.2
N20446174: TP9.1(TP) U1.A2(BG)
N20447902: D1.2(CATHODE) R37.1
N20475697: R138.1 U11.14(B1)
N20475701: R139.1 U11.13(B2)
N20475713: R140.1 U11.12(B3)
N20475725: R141.1 U11.11(B4)
N20475883: R142.1 U11.9(OEB)
N20476138: R142.2 SJP14.1
N20477206: R133.1 U10.14(B1)
N20477210: R134.1 U10.13(B2)
N20477222: R135.1 U10.12(B3)
N20477234: R132.2 R136.1 U10.11(B4)
N20477346: SJP3.2(PIN2) U10.3(A1)
N20477348: SJP4.2(PIN2) U10.4(A2)
N20477350: SJP5.2(PIN2) U10.5(A3)
N20477352: SJP6.2(PIN2) U10.6(A4)
N20477392: R137.1 U10.9(OEB)
N20478124: R110.1 U7.4(Y)
N20479286: R143.1 U12.14(B1)
N20479288: R144.1 U12.13(B2)
N20479290: R145.1 U12.12(B3)
N20479292: R146.1 U12.11(B4)
N20479340: R147.1 U12.9(OEB)
N20479396: R147.2 SJP13.1
N20523656: TP10.1(TP) U1.B9(CALSTAT)
N20560674: J25.C39 J25.D36 J25.D38 J25.D40 R105.1
N20560927: J25.D1 J26.1
N20597236: J30.2 R108.1
N20601243: D10.1(ANODE) U15.7(OUTB)
N20601382: D11.1(ANODE) U15.1(OUTA)
N20601403: D10.2(CATHODE) R185.1
N20601859: D11.2(CATHODE) R32.1
N20602433: C14.2 D9.2(CATHODE) R184.1 U15.5(INB+)
N20603216: C3.2 D12.2(CATHODE) R31.1 U15.3(INA+)
N20603624: C4.2 R30.2 R33.1 U15.2(INA-) U15.6(INB-)
N20606076: J9.1 R20.2
N20606250: J8.1 R19.2
N20759391: C261.2 R197.1 R198.2 U16.9(ADJ)
N20760406: C266.2 R199.1 R200.2 U17.9(ADJ)
N20770678: R205.1 SJP17.3(PIN3) U19.2(EN) U19.3(VIN#3) U19.4(VIN#4) U19.5(VIN#5) U19.6(VIN#6)
N20770696: C272.1 U19.1(SS)
N20770708: C273.1 U19.15(COMP)
N20770710: C228.1 C231.1 C273.2 R203.2 R206.1 R222.1 U19.11(VOUT#11) U19.12(VOUT#12) U19.13(VOUT#13) U19.14(VOUT#14)
N20770722: R203.1 U19.9(PWRGD)
N20770740: R204.1 U19.7(PCL)
N20770762: R205.2 U19.10(CS)
N20770834: C226.1 R206.2 R207.1 U19.16(FB)
N20771140: C254.2 R191.1 R202.1 U18.17(VSENSE)
N20771180: C269.1 R201.2
N20771182: C271.1 R201.1 U18.18(COMP)
N20771289: R190.2 U18.20(PWRGD)
N20771323: R193.2 R196.2 R223.2 U18.2(EN)
N20771329: R195.1 U18.3(RT)
N20771355: C258.1 U18.19(SS/TR)
N20771381: C251.1 U18.16(BOOT)
N20771385: C251.2 L6.1 U18.11(PH1) U18.12(PH2) U18.13(PH3) U18.14(PH4) U18.15(PH5)
N20772111: C217.2 R211.1 R221.1 U14.17(VSENSE)
N20772147: C225.1 R215.2
N20772149: C216.1 R215.1 U14.18(COMP)
N20772286: R212.2 R214.2 U14.2(EN)
N20772300: R213.2 U14.3(RT)
N20772322: C215.1 U14.19(SS/TR)
N20772348: C221.1 U14.16(BOOT)
N20772352: C221.2 L7.1 U14.11(PH1) U14.12(PH2) U14.13(PH3) U14.14(PH4) U14.15(PH5)
N20774965: R218.1 SJP15.3(PIN3) U20.2(EN) U20.3(VIN#3) U20.4(VIN#4) U20.5(VIN#5) U20.6(VIN#6)
N20775006: C211.1 U20.1(SS)
N20775018: C210.1 U20.15(COMP)
N20775020: C127.1 C206.1 C210.2 R216.2 R220.1 SJP16.1(PIN1) U20.11(VOUT#11) U20.12(VOUT#12) U20.13(VOUT#13) U20.14(VOUT#14)
N20775032: R216.1 U20.9(PWRGD)
N20775050: R217.1 U20.7(PCL)
N20775064: R218.2 U20.10(CS)
N20775144: C207.1 R219.1 R220.2 U20.16(FB)
N20776452: FB16.1 FB17.1 SJP16.2(PIN2)
N20809211: R178.1 U8.44(CDBUS5)
N20814533: R224.1 U18.4(SYNC)
N20837548: R118.2 SJP7.3(PIN3)
N20837573: R119.2 SJP8.3(PIN3)
N20837587: R120.2 SJP9.3(PIN3)
N20837623: R121.2 SJP10.3(PIN3)
N20837793: SJP11.3(PIN3) U8.43(CDBUS4)
N20837816: R178.2 SJP12.3(PIN3)
N20965250: R137.2 SJP2.1
N198851401: C131.2 R66.1
N198852420: C128.2 R63.1

Pads without a net: J25 A22 A23 A26 A27 A30 A31 A34 A35 A38 A39 B1 B2 B19 B20 B21 B24 B25 B28 B29 B32 B33 B36 B37 B40 C2 C3 C4 C10 C11 C12 C13 C14 C15 C16 C17 C18 C19 C20 C22 C23 C26 C27 D2 D8 D9 D10 D11 D12 D13 D14 D15 D16 D17 D18 D19 D20 D21 D22 D23 D24 D27 D29 D33 D34 E1 E2 E3 E4 E5 E6 E7 E8 E9 E10 E11 E12 E13 E14 E15 E16 E17 E18 E19 E20 E21 E22 E23 E24 E25 E27 E28 E30 E31 E33 E34 E36 E37 F2 F3 F4 F5 F6 F7 F8 F10 F11 F12 F13 F14 F15 F16 F17 F18 F19 F20 F21 F22 F23 F24 F25 F26 F28 F29 F31 F32 F34 F35 F37 F38 G1 G2 G3 G4 G15 G16 G17 G18 G19 G20 G22 G23 G25 G28 G30 G31 H1 H3 H4 H5 H6 H7 H8 H9 H10 H11 H12 H13 H14 H15 H16 H17 H18 H19 H20 H21 H22 H23 H24 H25 H26 H32 H34 H35 J1 J2 J3 J4 J5 J6 J7 J8 J9 J10 J11 J12 J13 J14 J16 J17 J18 J19 J20 J21 J22 J23 J24 J25 J27 J28 J30 J31 J33 J34 J36 J37 K1 K2 K3 K4 K5 K6 K7 K8 K9 K10 K11 K12 K13 K14 K15 K16 K17 K18 K19 K20 K21 K22 K23 K24 K25 K26 K28 K29 K31 K32 K34 K35 K37 K38 L1 L2 L3 L4 L5 L6 L7 L8 L9 L10 L11 L12 L13 L14 L15 L16 L17 L18 L19 L20 L21 L22 L23 L24 L25 L26 L27 L28 L29 L32 L33 L36 L37 L40 M1 M2 M3 M4 M5 M6 M7 M8 M9 M10 M11 M12 M13 M14 M15 M16 M17 M18 M19 M20 M21 M22 M23 M24 M25 M26 M27 M30 M31 M34 M35 M38 M39 Y1 Y2 Y3 Y6 Y7 Y26 Y27 Y30 Y31 Y34 Y35 Y38 Y39 Z4 Z5 Z8 Z9 Z24 Z25 Z28 Z29 Z32 Z33 Z36 Z37 Z40; J31 4; NOREF 1; NOREF#12 1; NOREF#43 1; NOREF#84 1; NOREF#86 1; NOREF#87 1; NOREF#88 1; NOREF#89 1; NOREF#90 1; NOREF#91 1; NOREF#92 1; T2 2; U3 5 28 32; U4 7 8 9 22 23 24 25 29 30 49 50 56 57 60 61; U5 7; U6 4; U8 21 22 23 24 30 32 33 34 36 45 46 60; U9 6 7; U13 1 3; U16 5; U17 5

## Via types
v1: diameter 0.508, hole 0.254, TOP to BOTTOM, 2110 vias
v2: diameter 0.457, hole 0.203, TOP to BOTTOM, 7 vias
v3: diameter 0.559, hole 0.305, TOP to BOTTOM, 56 vias
v4: diameter 0.762, hole 0.381, TOP to BOTTOM, 275 vias
v5: diameter 0.61, hole 0.33, TOP to BOTTOM, 16 vias

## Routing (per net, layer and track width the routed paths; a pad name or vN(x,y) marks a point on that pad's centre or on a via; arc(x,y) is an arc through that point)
1.538V:
  vias: v1(61.98,8.76) v1(62.1,10.41) v1(63.88,8.76) v1(64.9,12.06) v1(65.66,8.76) v1(67.18,12.06) v1(67.94,17.14) v1(68.07,14.73) v1(68.07,9.65) v1(68.07,5.97) v1(68.07,4.45) v1(68.89,5.21) v1(69.22,7.75) v1(69.6,5.97) v1(69.6,4.45) v1(69.98,11.81) v1(70.23,1.4) v1(71.25,3.05) v1(71.37,6.6) v1(71.5,9.53) v1(71.63,16.51) v1(71.63,14.73) v1(73.28,2.29) v1(73.79,1.52) v1(74.8,17.14)
3.3VCLK:
  vias: v1(23.04,149.48) v1(23.04,148.21) v1(23.04,146.94) v1(25.02,148.46) v1(25.91,149.35) v1(26.8,148.46) v1(28.07,149.35) v1(28.32,148.46) v1(28.45,147.45) v1(28.83,146.69) v1(28.83,145.03) v1(29.59,149.61) v1(29.59,148.34) v1(29.72,145.03) v1(29.84,147.57) v1(30.48,149) v1(30.73,146.69) v1(30.73,145.03) v1(31.24,147.45) v1(31.37,149.61) v1(31.37,148.34) v1(32.64,149.99) v1(32.64,148.72) v1(33.91,148.97) v1(34.29,149.99) v1(34.29,147.96) v1(34.8,149) v1(35.69,148.97) v1(35.94,149.99) v1(35.94,147.96)
3.3VLMX:
  vias: v1(23.8,135.26) v1(23.8,133.99) v1(23.8,132.72) v1(25.65,135.13) v1(25.78,134.24) v1(27.43,135.13) v1(27.56,134.24) v1(28.96,134.24) v1(29.21,130.56) v1(29.34,135.13) v1(29.34,131.95) v1(29.46,133.22) v1(30.48,135.38) v1(30.61,130.43) v1(30.73,133.22) v1(30.99,131.95) v1(31.24,134.77) v1(32,135.38) v1(32,134.11) v1(32.13,130.68) v1(32.26,133.22) v1(33.15,132.21) v1(33.4,135.64) v1(33.66,134.11) v1(34.67,134.75) v1(34.8,135.64) v1(34.93,132.33) v1(35.18,133.73) v1(35.56,134.77) v1(36.45,134.75) v1(36.58,135.64)
5.0V_IN: length 24.6
  BOTTOM w0.127: v3(24.41,27.44) 24.42,27.43 v3(25.39,27.43) ; v3(24.41,27.44) 24.41,26.45 v3(24.39,26.43) ; v3(24.41,27.44) 23.4,27.44 v3(23.39,27.43) ; v3(24.41,27.44) 24.39,27.46 v3(24.39,28.43) ; v3(24.39,26.43) v3(23.39,26.43) ; v3(24.39,26.43) v3(24.39,25.43) ; v3(24.39,26.43) v3(25.39,26.43) ; v3(23.39,26.43) v3(23.39,27.43) ; v3(23.39,26.43) v3(23.39,25.43) ; v3(23.39,28.43) v3(23.39,29.43) ; v3(23.39,28.43) v3(24.39,28.43) ; v3(23.39,28.43) v3(23.39,27.43) ; v3(23.39,29.43) v3(24.39,29.43) ; v3(23.39,29.43) 23.3,29.34 Q3.8 ; Q3.5 23.3,25.53 v3(23.39,25.43) ; v3(24.39,25.43) v3(25.39,25.43) v3(25.39,26.43) ; v3(24.39,25.43) v3(23.39,25.43) ; v3(24.39,28.43) v3(24.39,29.43) ; v3(24.39,28.43) v3(25.39,28.43) ; v3(25.39,28.43) v3(25.39,29.43) v3(24.39,29.43) ; v3(25.39,28.43) v3(25.39,27.43) ; v3(25.39,27.43) v3(25.39,26.43)
  vias: v1(11.68,31.11) v1(11.68,26.16) v1(11.68,24.38) v1(12.83,32.26) v1(13.59,26.16) v1(13.59,24.38) v1(13.72,33.15) v1(15.37,26.16) v1(15.37,24.38) v1(15.49,35.43) v1(17.08,46.7) v1(17.2,56.1) v1(17.33,51.4) v1(18.16,33.91) v1(18.16,31.37) v1(18.67,24.38) v1(18.85,48.1) v1(19.3,34.67) v1(19.43,30.86) v1(20.76,54.19) v1(20.89,48.1) v1(20.89,46.57) v1(21.01,51.4) v1(21.21,24.38) v1(21.46,32.64) v1(22.35,36.96) v1(22.35,36.07) v1(22.66,54.19) v1(22.66,51.4) v1(22.86,32.38) v1(23.62,31.37) v1(24.44,56.1) v1(24.44,54.19) v1(24.57,46.57) v1(24.64,30.23) v1(25.27,38.99) v1(25.4,24.38)
5VIN: length 21.1
  BOTTOM w0.279: v1(60.96,16) 63.5,16 65.28,17.78 65.28,26.04 63.63,27.69 63.63,28.7 62.61,29.72 62.61,30.35 v1(60.96,32)
  vias: v1(6.35,151.77) v1(6.35,150.5) v1(7.11,137.54) v1(7.11,136.27) v1(7.24,151.1) v1(8,136.88) v1(8.13,151.77) v1(8.13,150.5) v1(8.89,137.54) v1(8.89,136.27) v1(9.6,155.07) v1(9.6,153.8) v1(9.6,152.53) v1(9.6,151.26) v1(9.65,149.99) v1(9.65,148.34) v1(10.36,141.35) v1(10.36,140.08) v1(10.36,138.81) v1(10.36,137.54) v1(10.41,136.14) v1(10.41,134.75) v1(11.3,154.56) v1(11.3,153.16) v1(11.25,152.02) v1(11.25,150.75) v1(11.25,149.48) v1(11.25,148.21) v1(12.01,137.8) v1(12.01,136.53) v1(12.01,135.26) v1(12.01,133.99) v1(12.07,139.19) v1(12.19,140.97) v1(25.91,32.38) v1(26.67,31.37) v1(27.56,30.61) v1(27.66,29.34) v1(27.66,28.07) v1(27.66,26.8) v1(27.81,32.77) v1(27.81,31.62) v1(29.46,28.57) v1(29.46,27.2) v1(30.61,31.11) v1(30.99,31.88) v1(31.11,32.89) v1(31.37,30.23) v1(31.37,28.96) v1(32.13,29.59) v1(32.26,31.88) v1(32.64,32.89) v1(32.89,30.23) v1(32.89,28.96) v1(33.66,31.88) v1(33.91,29.59) v1(34.16,32.89) v1(34.42,31.11) v1(34.93,31.88) v1(35.56,30.86) v1(38.86,24.64) v1(38.99,8.64) v1(39.37,25.91) v1(39.37,9.91) v1(39.75,31.62) v1(39.75,29.97) v1(39.75,14.1) v1(40.01,24.64) v1(40.13,8.64) v1(40.51,30.1) v1(40.51,14.1) v1(40.64,26.29) v1(40.64,25.27) v1(41.15,9.78) v1(41.53,23.88) v1(41.53,7.87) v1(42.16,10.03) v1(42.16,9.02) v1(42.29,26.29) v1(42.29,25.27) v1(42.55,24.13) v1(42.55,8) v1(42.8,9.53) v1(43.87,26.16) v1(43.87,24.89) v1(43.85,23.62) v1(43.87,10.16) v1(43.87,8.89) v1(43.85,7.62)
+2.2V:
  vias: v1(61.85,26.67) v1(62.23,26.16) v1(62.36,24.13) v1(64.39,24.13) v1(64.9,28.07) v1(66.42,28.07) v1(66.93,24.13) v1(67.82,31.5) v1(67.94,29.34) v1(67.94,21.97) v1(67.94,20.32) v1(68.89,21.21) v1(69.22,26.67) v1(69.47,27.94) v1(69.6,26.16) v1(69.6,24.13) v1(69.72,21.97) v1(69.85,20.32) v1(69.98,34.93) v1(70.23,30.23) v1(71.5,20.07) v1(71.63,37.72) v1(71.63,25.27) v1(71.88,21.97) v1(72.01,35.31) v1(72.01,27.94) v1(73.15,34.29) v1(73.15,30.73) v1(73.41,27.81) v1(74.04,23.62) v1(74.42,23.11) v1(74.8,22.61) v1(75.06,26.8) v1(75.06,25.15) v1(75.06,20.19) v1(75.44,38.35) v1(75.56,34.42) v1(75.95,25.93) v1(76.58,27.81) v1(76.84,26.8) v1(76.96,38.48) v1(76.96,25.15)
+3.3V_LMX: length 14.9
  TOP w0.279: C106.1 62.94,135.35 v1(62.96,135.33)
  TOP w0.381: C113.1 C101.1 v1(57.79,139.61) ; v1(66.13,138.67) 66.07,138.61 64.73,138.61 C100.1 ; C103.1 v1(64.39,135.73) ; C102.2 62.13,135.86 C106.1 ; v1(62.59,145.05) v1(62.59,143.96)
  BOTTOM w0.279: v1(62.59,143.96) 62.8,143.74 62.8,143.59 62.83,143.57 62.83,143.14 62.8,143.12 U3.37 ; v1(62.96,135.33) 62.58,135.33 62.3,135.61 U3.15
  BOTTOM w0.305: U3.7 66.07,138.61 v1(66.13,138.67) ; v1(58.4,136.21) 58.4,136.85 58.66,137.11 U3.21 ; v1(64.39,135.73) 64.3,135.82 U3.11 ; U3.26 v1(57.79,139.61)
  vias: v1(37.59,131.83) v1(37.57,130.56) v1(37.59,129.03) v1(37.97,132.33) v1(37.97,129.79) v1(38.35,132.84) v1(38.35,131.06) v1(38.86,132.33) v1(38.86,129.03) v1(38.99,130.3) v1(39.24,131.44) v1(39.75,132.33) v1(39.85,130.68) v1(39.88,129.29) v1(57.41,141.24) v1(68.18,141.8)
+3.3V_LMXRF: length 4.1
  TOP w0.381: v1(56.87,136.34) C99.1 v1(56.87,139.39)
  BOTTOM w0.254: R49.2 60.48,134.11 v1(60.53,134.06) 60.96,134.06 R48.2
  vias: v1(25.02,132.46) v1(25.02,131.32) v1(25.02,130.18) v1(25.02,129.03) v1(25.02,127.89) v1(25.02,126.75) v1(25.78,130.81) v1(25.91,132.46) v1(25.91,128.4) v1(26.29,131.95) v1(26.52,129.92) v1(26.54,127.13) v1(26.67,131.44) v1(26.67,130.81) v1(26.82,128.65)
+3.3VCLK: length 3.8
  TOP w0.279: FB10.1 93.83,130.5 v1(94.21,130.88)
  TOP w0.508: FB2.1 v1(90.91,120.34) ; v1(98.27,117.67) 98.15,117.55 96.75,117.55 FB5.1
  vias: v1(33.4,142.24) v1(33.78,145.03) v1(34.16,143.64) v1(34.16,142.88) v1(34.16,142.11) v1(34.8,145.67) v1(34.8,144.27) v1(34.93,142.62) v1(35.56,145.03) v1(35.66,143.38) v1(35.69,141.99) v1(78.34,126.56) v1(80.75,145.36) v1(86.97,127.48) v1(86.97,125.6) v1(88.75,134.38) v1(88.76,133.74) v1(88.82,133.11) v1(89.38,134.08) v1(89.36,133.28) v1(89.77,120.29) v1(90.32,120.31) v1(90.52,119.78) v1(99.8,117.67) v1(102.08,117.8) v1(103.1,131.01) v1(106.17,130.94) v1(107.67,124.4)
GND: length 102.8
  TOP w0.254: U8.13 54.02,59.34 54.01,59.34 53.59,59.34 53.58,59.34 v1(53.35,59.34) ; 53.77,60.5 53.67,60.59 v1(53.67,60.76) 53.76,60.84 U8.10 ; U12.7 82.84,68.35 v1(83.07,68.58) ; C77.2 v1(26.11,88.98) ; U12.10 86.47,68.35 v1(86.25,68.58) ; U12.2 v1(83.04,71.6) ; U2.5 v1(11.25,127.2) ; v1(53.59,58.29) 53.64,58.34 U8.15 ; v1(59.05,55.65) 59.31,55.9 59.31,56.01 ; v1(54.48,65.65) 54.48,66.03 v1(54.69,66.24) ; U8.35 64.68,58.84 v1(64.69,58.85) ; U11.10 v1(82.06,58.61) ; 101.07,121.99 101.58,121.48 C157.2 ; U2.6 v1(9.5,126.14) ; v1(61.81,67.05) U8.51 ; U12.8 v1(81.95,66.94) ; U12.1 v1(80.8,72.25)
  TOP w0.279: R99.2 v1(105.77,125.89) ; 53.77,60.5 53.83,60.43 54.39,60.43 U8.11 ; C114.1 56.19,141.19 v1(55.55,140.55) ; T2.4 v1(17.02,94.49)
  TOP w0.305: C109.2 56.16,140.43 v1(56.11,140.48) ; U8.5 v1(53.24,63.35) ; v2(63.32,134.75) 63.31,134.74 C106.2 ; U8.1 v1(54.48,65.65) ; 59.31,56.01 U8.25 ; U8.47 v1(64.72,64.85)
  TOP w0.356: U10.10 v1(50.77,36.09) ; U10.7 v1(42.14,36.09)
  TOP w0.381: C163.2 101.2,122.88 101.07,123.01 ; C102.1 62.33,137.61 v5(62.56,137.84) ; C165.2 96.24,128.34 95.99,128.09 ; 94.97,121.99 94.46,121.48 C155.1 ; C103.2 65.32,136.29 v1(65.55,136.07) ; 100.05,121.99 99.8,121.74 C158.2 ; 97,121.99 97.26,121.74 C159.2 ; v5(63.58,137.84) 64.19,137.23 C104.1 ; v5(60.53,140.89) 60.53,140.84 C113.2 ; v5(60.53,139.87) 60.36,139.87 C101.2 ; C100.2 63.83,138.6 v5(63.58,138.86) ; 94.97,123.01 94.46,122.5 C156.1 ; 101.07,128.09 101.58,128.59 C166.2 ; v1(63.35,145.36) 63.05,145.66 C107.1 ; C99.2 55.98,137.59 v1(55.98,136.51) ; 101.07,124.02 101.32,124.28 C154.1
  TOP w0.508: v1(101.22,59.05) 101.47,58.8 U15.4 ; C164.2 v1(106.17,123.7) ; R106.2 v1(130.84,112.5)
  L11_GND-6 w0.203: 123.9,102.69 123.88,102.69 123.87,102.69 ; 123.9,101.98 123.88,101.98 123.87,101.98
  BOTTOM w0.152: U3.13 63.3,137.57 v5(63.58,137.84) ; v1(41.42,101.26) 40.98,100.81 40.63,100.81 40.61,100.8 40.24,100.8 40.22,100.81 40.06,100.81 39.92,100.67 C90.2 ; 38.43,94.26 v1(38.43,94.26)
  BOTTOM w0.254: C169.2 52.65,64.08 v1(52.45,63.88) ; U3.25 60.27,139.11 v5(60.53,138.86) ; U3.14 62.8,137.6 v5(62.56,137.84) ; C65.2 38.43,94.26 ; C57.2 28.43,97.26 v1(28.43,97.26) ; 38.01,91.81 37.87,91.81 v1(37.42,92.26) ; C78.2 v1(32.43,90.26) ; v1(31.42,93.26) 31.42,93.26 C61.2 ; R52.1 v1(62.03,130.8) ; C54.2 31.06,99.26 v1(31.42,99.26) ; R189.2 R188.2 89.95,125.42 v1(89.77,125.6) ; v1(53.35,59.34) 53.43,58.46 v1(53.59,58.29) ; C88.2 v1(38.43,96.26) ; v1(29.42,95.26) C58.2 ; 63.8,141.11 U3.2 ; 63.8,141.11 U3.39 ; 63.8,141.11 v5(63.58,140.89) ; v1(93.47,116.91) 93.65,116.73 R63.2 ; C75.2 v1(30.43,101.26) ; R53.1 v1(58.98,130.58) ; C182.2 54.48,60.22 54.21,60.22 v1(53.67,60.76) ; v1(31.42,90.26) 31.43,90.26 C79.2 ; v5(61.55,140.89) 61.3,141.13 U3.34 ; U3.4 63.82,140.11 v5(63.58,139.87) ; C73.2 v1(32.43,101.26) ; C24.1 v1(88.88,124.53) ; U3.6 63.84,139.11 v5(63.58,138.86) ; C137.1 90.16,123.02 v1(90.15,123.01) ; C62.2 v1(31.42,95.26) ; C188.2 62.48,57.96 ; v1(31.42,101.26) 31.43,101.26 C74.2 ; C63.2 v1(31.42,94.26) ; v1(31.42,98.26) 31.05,98.26 C55.2 ; C181.2 54.69,65.86 v1(54.48,65.65) ; C56.2 31.03,97.26 v1(31.42,97.26) ; C92.2 38.43,92.26 v1(38.43,92.26) ; C80.2 v1(30.43,90.26) ; v1(31.42,96.26) C59.2 ; C71.2 28.82,90.65 v1(28.43,90.26) ; C81.2 v1(27.15,101.57) ; C60.2 v1(31.42,92.26) ; v1(61.81,67.05) 61.81,67.09 61.42,67.47 61.42,67.56 C176.2 ; 28.99,100.7 28.99,100.7 v1(28.43,101.26)
  BOTTOM w0.279: J25.C1 140.34,111.12 140.72,111.51 142.24,111.51 v1(142.88,110.87) ; C89.2 v1(37.42,99.26) ; v1(140.34,81.66) J25.B23 J25.B22 ; U3.40 v1(64.3,143.39) ; v1(38.43,97.26) 38.43,97.25 C87.2 ; C86.2 v1(38.43,98.26) ; v1(38.43,99.26) 38.43,99.26 C85.2 ; C91.2 v1(36.43,91.26) ; C64.2 v1(38.43,93.26) ; v1(140.34,101.98) J25.C9 ; v5(62.56,139.87) U3.41 ; C96.2 v1(38.43,95.26) ; C183.2 63.75,59.03 63.74,59.02 ; v1(135.25,101.98) J25.F9 ; v1(139.06,104.52) J25.D7 ; v1(27.74,93.09) 28.41,92.49 C82.2 ; 61.86,62.35 61.87,62.36 C187.2 ; U3.31 v1(59.08,142.39)
  BOTTOM w0.305: C195.2 v1(89.19,71.73) ; v1(32,36.58) C175.2
  BOTTOM w0.381: R23.2 v1(36.58,123.19)
  BOTTOM w0.508: v1(28.43,102.26) 27.3,103.38 R26.2 ; C175.2 29.95,36.58 v1(29.84,36.68) ; v1(78.97,73.19) 78.52,72.75 C180.2
  vias: v1(0.38,71.63) v1(0.38,69.09) v1(0.38,58.93) v1(0.38,56.39) v1(0.51,101.47) v1(0.51,92.58) v1(0.51,74.8) v1(0.51,65.91) v1(0.51,62.1) v1(0.51,53.21) v1(0.7,98.29) v1(0.7,95.77) v1(0.89,141.35) v1(0.89,139.07) v1(0.89,136.65) v1(0.89,134.24) v1(0.89,131.7) v1(0.89,128.52) v1(0.89,125.98) v1(0.89,123.06) v1(0.89,120.52) v1(0.89,118.24) v1(1.02,150.5) v1(1.02,147.41) v1(1.02,145.42) v1(1.02,143.38) v1(0.95,115.55) v1(0.95,113.01) v1(0.95,110.09) v1(0.95,107.55) v1(0.95,105.77) v1(0.95,103.23) v1(1.02,32.89) v1(1.02,27.81) v1(1.02,25.27) v1(1.02,21.97) v1(1.02,19.43) v1(1.02,15.88) v1(1.02,13.34) v1(1.02,10.29) v1(1.02,7.75) v1(1.02,4.57) v1(1.02,2.03) v1(1.02,1.02) v1(1.07,90.02) v1(1.07,87.48) v1(1.07,84.94) v1(1.07,82.4) v1(1.07,79.73) v1(1.07,77.19) v1(1.07,37.57) v1(1.07,35.03) v1(1.14,30.35) v1(1.27,44.58) v1(1.27,42.04) v1(1.52,156.3) v1(1.52,101.47) v1(1.52,92.58) v1(1.52,74.8) v1(1.52,65.91) v1(1.52,62.1) v1(1.52,53.21) v1(1.66,48.9) v1(1.66,47.63) v1(1.66,40) v1(1.66,38.73) v1(2.29,71.63) v1(2.29,69.09) v1(2.29,58.93) v1(2.29,56.39) v1(2.54,101.47) v1(2.6,98.29) v1(2.6,95.77) v1(2.54,92.58) v1(2.54,74.8) v1(2.54,65.91) v1(2.54,62.1) v1(2.54,53.21) v1(2.55,48.27) v1(2.55,39.36) v1(3.44,48.9) v1(3.44,47.63) v1(3.44,40) v1(3.44,38.73) v1(3.56,101.47) v1(3.56,92.58) v1(3.56,74.8) v1(3.56,65.91) v1(3.56,62.1) v1(3.56,53.21) v1(3.56,1.02) v1(4.19,71.63) v1(4.19,69.09) v1(4.19,58.93) v1(4.19,56.39) v1(4.51,98.29) v1(4.51,95.77) v1(4.57,101.47) v1(4.57,92.58) v1(4.57,74.8) v1(4.57,65.91) v1(4.57,62.1) v1(4.57,53.21) v1(5.21,156.3) v1(5.46,101.27) v1(6.1,71.63) v1(6.1,69.09) v1(6.1,58.93) v1(6.1,56.39) v1(6.41,98.29) v1(6.41,95.77) v1(6.48,145.92) v1(6.48,144.65) v1(6.73,1.02) v1(7.12,48.9) v1(7.12,47.63) v1(7.12,40) v1(7.12,38.73) v1(7.24,145.31) v1(7.24,131.7) v1(7.24,130.43) v1(7.24,42.16) v1(7.75,156.3) v1(8,145.92) v1(8,144.65) v1(8,131.09) v1(8,71.63) v1(8,69.09) v1(8,58.93) v1(8,56.39) v1(8.05,48.27) v1(8.05,39.36) v1(8.15,42.22) v1(8.32,98.29) v1(8.32,95.77) v1(8.76,131.7) v1(8.76,130.43) v1(8.89,1.02) v1(9.02,42.16) v1(9.03,48.9) v1(9.03,47.63) v1(9.03,40) v1(9.03,38.73) v1(9.91,71.63) v1(9.91,69.09) v1(9.91,58.93) v1(9.91,56.39) v1(10.04,66.84) v1(10.04,64.04) v1(10.03,61.73) v1(10.22,98.29) v1(10.22,95.77) v1(10.67,123.32) v1(10.67,122.17) v1(11.05,1.02) v1(11.96,70.76) v1(12.13,98.29) v1(12.13,95.77) v1(12.27,57.81) v1(12.56,68.77) v1(12.57,66.49) v1(12.58,61.55) v1(12.58,59.98) v1(12.93,90.68) v1(13.26,156.3) v1(13.46,1.02) v1(14.03,98.29) v1(14.03,95.77) v1(15.49,91.95) v1(15.88,90.98) v1(15.88,89.71) v1(15.97,98.29) v1(15.97,95.77) v1(16.51,0.89) v1(16.56,156.3) v1(16.64,90.35) v1(17.14,97.03) v1(17.28,95.75) v1(17.4,91.95) v1(17.4,90.98) v1(17.4,89.71) v1(18.29,98.17) v1(18.29,93.34) v1(19.1,156.3) v1(19.3,88.52) v1(19.3,85.34) v1(19.68,0.89) v1(21.84,97.66) v1(21.84,93.85) v1(22.22,0.89) v1(22.4,156.3) v1(22.48,113.1) v1(22.48,78.41) v1(22.86,97.14) v1(22.86,94.37) v1(22.99,97.79) v1(22.99,93.73) v1(23.37,34.8) v1(23.37,34.04) v1(23.52,92.83) v1(23.52,90.65) v1(23.88,97.16) v1(23.88,94.36) v1(24.38,85.22) v1(24.94,156.3) v1(25.15,113.1) v1(25.15,78.41) v1(25.27,0.89) v1(25.4,85.22) v1(25.53,101.07) v1(25.53,86.49) v1(26.8,154.31) v1(27.05,97.54) v1(27.05,93.98) v1(27.18,141.61) v1(27.48,128.65) v1(27.43,37.21) v1(27.43,36.45) v1(27.58,143) v1(27.56,140.08) v1(27.74,98.27) v1(27.81,0.89) v1(27.94,36.83) v1(28.09,129.92) v1(28.24,156.3) v1(28.43,94.26) v1(28.43,89.26) v1(28.45,37.21) v1(28.45,36.45) v1(28.96,32.77) v1(29.16,110.62) v1(29.21,82.8) v1(29.16,80.9) v1(29.46,108.58) v1(29.42,96.26) v1(29.46,25.63) v1(29.61,111.28) v1(29.61,80.24) v1(29.84,155.45) v1(29.84,154.18) v1(29.84,32) v1(29.97,0.89) v1(30.23,105.79) v1(30.23,104.52) v1(30.23,87) v1(30.23,85.72) v1(30.4,111.53) v1(30.4,79.98) v1(30.48,154.79) v1(30.48,141.22) v1(30.48,139.95) v1(30.43,102.26) v1(30.43,89.26) v1(30.68,118.24) v1(30.68,116.71) v1(30.68,74.8) v1(30.68,73.28) v1(30.78,156.3) v1(30.8,54.1) v1(30.8,49.02) v1(31.14,117.58) v1(31.14,116.71) v1(31.19,112.37) v1(31.19,111.28) v1(31.19,80.24) v1(31.19,79.15) v1(31.14,74.8) v1(31.14,73.94) v1(31.24,140.56) v1(31.37,155.45) v1(31.37,154.18) v1(31.37,27.18) v1(31.37,26.04) v1(31.65,110.62) v1(31.65,80.9) v1(31.93,117.32) v1(31.93,74.19) v1(32.07,54.1) v1(32.07,49.02) v1(32.2,110.62) v1(32.2,80.9) v1(32.13,26.54) v1(32.43,99.26) v1(32.43,98.26) v1(32.43,97.26) v1(32.43,96.26) v1(32.43,95.26) v1(32.43,94.26) v1(32.43,93.26) v1(32.43,92.26) v1(32.51,0.89) v1(32.72,143.26) v1(32.71,117.58) v1(32.71,116.71) v1(32.66,111.28) v1(32.66,80.24) v1(32.66,79.15) v1(32.71,74.8) v1(32.71,73.94) v1(32.77,27.18) v1(32.77,25.91) v1(32.92,38.23) v1(33.17,118.24) v1(33.17,116.71) v1(33.17,74.8) v1(33.17,73.28) v1(33.4,156.21) v1(33.34,54.1) v1(33.34,49.02) v1(33.45,111.53) v1(33.42,102.26) v1(33.42,101.26) v1(33.42,100.26) v1(33.42,99.26) v1(33.42,98.26) v1(33.42,97.26) v1(33.42,96.26) v1(33.42,95.26) v1(33.42,94.26) v1(33.42,93.26) v1(33.42,92.26) v1(33.42,91.26) v1(33.42,90.26) v1(33.42,89.26) v1(33.45,79.98) v1(33.53,105.79) v1(33.53,104.52) v1(33.53,87) v1(33.53,85.72) v1(34.04,151.77) v1(34.24,111.28) v1(34.24,80.24) v1(34.42,108.58) v1(34.43,100.26) v1(34.43,99.26) v1(34.43,98.26) v1(34.43,97.26) v1(34.43,96.26) v1(34.43,95.26) v1(34.43,94.26) v1(34.43,93.26) v1(34.43,92.26) v1(34.43,91.26) v1(34.54,82.8) v1(34.69,110.62) v1(34.69,80.9) v1(34.8,151.74) v1(34.8,137.54) v1(35.42,100.26) v1(35.42,99.26) v1(35.42,98.26) v1(35.42,97.26) v1(35.42,96.26) v1(35.42,95.26) v1(35.42,94.26) v1(35.42,93.26) v1(35.42,92.26) v1(35.42,91.26) v1(35.43,29.59) v1(35.56,137.52) v1(35.69,151.77) v1(35.69,0.89) v1(36.45,137.54) v1(36.43,100.26) v1(36.43,99.26) v1(36.43,98.26) v1(36.43,97.26) v1(36.43,96.26) v1(36.43,95.26) v1(36.43,94.26) v1(36.43,93.26) v1(36.43,92.26) v1(36.43,90.26) v1(36.68,156.15) v1(36.7,141.99) v1(36.91,130.56) v1(37.03,66.37) v1(37.24,143.38) v1(37.42,98.26) v1(37.42,97.26) v1(37.42,96.26) v1(37.42,95.26) v1(37.42,94.26) v1(37.42,93.26) v1(37.59,145.03) v1(37.92,65.74) v1(37.85,13.97) v1(38.61,0.89) v1(38.73,113.1) v1(38.73,78.41) v1(38.81,64.97) v1(39.22,156.15) v1(39.37,120.78) v1(39.37,22.86) v1(39.37,6.86) v1(40.39,121.67) v1(40.39,120.78) v1(40.51,28.7) v1(40.51,12.7) v1(40.89,129.29) v1(41.35,113.1) v1(41.4,78.41) v1(41.43,130.68) v1(41.42,102.26) v1(41.42,90.26) v1(41.42,89.26) v1(41.53,31.37) v1(41.53,21.84) v1(41.53,5.84) v1(41.53,0.89) v1(41.78,132.33) v1(42.55,64.01) v1(43.31,103.23) v1(44.17,156.15) v1(44.7,0.89) v1(45.95,39.24) v1(46.71,156.15) v1(46.74,116.69) v1(46.74,114.04) v1(47.09,51.82) v1(47.24,0.89) v1(50.01,156.15) v1(50.42,0.89) v1(50.8,68.07) v1(50.8,61.98) v1(52.55,156.15) v1(52.62,144.47) v1(52.62,141.68) v1(52.62,138.88) v1(52.62,136.09) v1(52.65,61.34) v1(52.94,136.98) v1(53.21,0.89) v1(53.49,73) v1(54.03,142.69) v1(55.43,144.44) v1(55.5,0.89) v1(55.6,156.15) v1(55.96,142.54) v1(56.02,35.43) v1(57.38,124.78) v1(58.14,156.15) v1(58.17,0.89) v1(59.11,136.47) v1(59.57,142.79) v1(59.62,128.29) v1(59.72,121.23) v1(60.38,30.86) v1(60.38,14.86) v1(60.53,133.4) v1(60.81,145.49) v1(61.09,0.89) v1(61.44,156.15) v1(61.44,144.8) v1(61.47,128.26) v1(61.55,121.2) v1(61.95,145.28) v1(62.1,28.32) v1(62.1,12.32) v1(63.63,0.89) v1(63.86,144.01) v1(63.98,156.15) v1(64.18,51.88) v1(64.38,66.17) v1(64.39,30.23) v1(64.39,14.22) v1(64.72,145.05) v1(64.7,143.78) v1(64.7,142.21) v1(65.15,66.04) v1(65.28,10.41) v1(65.56,145.2) v1(65.56,143.78) v1(65.53,0.89) v1(65.63,53.78) v1(65.79,68.58) v1(65.79,26.42) v1(66.17,68.07) v1(66.55,68.58) v1(66.91,120.59) v1(67.03,156.15) v1(67.41,138.86) v1(67.44,26.42) v1(67.44,0.89) v1(68.53,145.05) v1(69.03,134.56) v1(69.14,124.1) v1(69.24,117.04) v1(69.37,145.23) v1(69.57,156.15) v1(70.72,136.24) v1(71,124.07) v1(71.07,117.01) v1(72.01,0.89) v1(72.87,156.15) v1(74.04,11.15) v1(74.04,9.75) v1(74.55,18.8) v1(74.55,0.89) v1(75.03,119.7) v1(75.06,10.52) v1(75.18,32.26) v1(75.18,30.99) v1(75.3,59.22) v1(75.41,156.15) v1(75.95,11.15) v1(75.95,9.75) v1(76.05,128.98) v1(76.05,127.83) v1(76.04,62.14) v1(76.38,144.98) v1(76.46,129.99) v1(76.58,1.91) v1(76.71,32.26) v1(76.71,30.99) v1(77.47,23.11) v1(77.98,0.89) v1(78.34,119.7) v1(78.49,17.78) v1(78.72,156.15) v1(78.74,39.12) v1(78.74,38.48) v1(78.74,37.85) v1(78.74,17.27) v1(78.99,16.76) v1(79.1,128.98) v1(79.38,23.75) v1(79.38,2.54) v1(79.55,126.68) v1(79.73,146.37) v1(79.89,129.74) v1(79.91,128.04) v1(80,60.49) v1(80.42,126.74) v1(80.52,0.89) v1(80.88,124.05) v1(80.95,125.75) v1(81.26,156.15) v1(81.59,128.04) v1(81.65,60.49) v1(81.92,129.74) v1(81.96,123.26) v1(82.15,143.83) v1(82.15,141.29) v1(82.15,138.75) v1(82.27,40.77) v1(82.27,19.56) v1(82.35,125.72) v1(82.43,127.35) v1(82.6,34.54) v1(82.6,12.95) v1(83.47,124.02) v1(83.54,127.5) v1(83.54,125.62) v1(83.57,0.89) v1(83.85,39.12) v1(83.85,37.59) v1(83.85,36.07) v1(83.85,17.91) v1(83.85,16.38) v1(83.85,14.86) v1(84.85,61.89) v1(85.1,72.26) v1(85.13,121.99) v1(85.57,156.28) v1(86.11,0.89) v1(87.35,123.41) v1(87.73,127.48) v1(87.73,125.6) v1(88.01,18.67) v1(88.27,40) v1(88.27,39.37) v1(88.27,38.73) v1(88.27,18.16) v1(88.37,156.28) v1(88.37,123.18) v1(88.5,121.05) v1(88.52,41.53) v1(88.52,20.32) v1(88.52,17.65) v1(88.62,129.66) v1(89.19,73.15) v1(89.15,16) v1(89.33,129.74) v1(89.53,62.52) v1(89.53,61.38) v1(89.53,60.24) v1(89.53,59.09) v1(89.64,131.9) v1(89.64,130.75) v1(89.66,15.49) v1(89.77,127.48) v1(89.92,0.89) v1(90.91,156.28) v1(91.04,129.61) v1(91.57,137.15) v1(91.57,134.84) v1(92.47,57.94) v1(92.46,0.89) v1(92.83,134.39) v1(92.88,132.23) v1(93.22,137.23) v1(93.22,134.92) v1(93.22,18.67) v1(93.47,40) v1(93.47,39.37) v1(93.47,38.73) v1(93.47,18.16) v1(93.73,17.65) v1(93.86,131.74) v1(94.1,134.25) v1(94.1,132.37) v1(94.21,156.28) v1(94.23,41.15) v1(94.35,73.5) v1(94.37,67.69) v1(94.64,127.1) v1(94.64,125.72) v1(94.64,124.35) v1(94.64,122.98) v1(95.3,114.94) v1(95.38,0.89) v1(95.51,118.18) v1(95.81,134.7) v1(95.96,128.42) v1(95.96,127.1) v1(95.96,125.72) v1(95.96,124.35) v1(95.96,122.98) v1(95.96,121.66) v1(97.34,128.42) v1(97.34,127.1) v1(97.34,125.72) v1(97.34,124.35) v1(97.34,122.98) v1(97.34,121.66) v1(97.51,156.28) v1(97.49,118.18) v1(97.69,114.94) v1(97.92,36.96) v1(97.92,15.75) v1(97.92,0.89) v1(98.2,134.7) v1(98.53,119.12) v1(98.58,40.26) v1(98.58,19.05) v1(98.71,128.42) v1(98.71,127.1) v1(98.71,125.72) v1(98.71,124.35) v1(98.71,122.98) v1(98.71,121.66) v1(98.68,17.65) v1(98.93,38.48) v1(99.06,33.4) v1(99.06,12.19) v1(99.19,16.89) v1(99.95,14.22) v1(100.05,156.28) v1(100.11,133.83) v1(100.08,128.42) v1(100.08,127.1) v1(100.08,125.72) v1(100.08,124.35) v1(100.08,122.98) v1(100.08,121.66) v1(100.08,59.05) v1(100.2,35.05) v1(100.46,13.46) v1(100.71,29.72) v1(100.71,8.51) v1(100.74,137.21) v1(101.4,127.1) v1(101.4,125.72) v1(101.4,124.35) v1(101.4,122.98) v1(101.78,132.13) v1(101.73,68.2) v1(101.99,133.83) v1(102.39,137.28) v1(102.47,135.25) v1(102.59,156.28) v1(102.72,129.92) v1(102.95,134.36) v1(103.25,0.89) v1(103.63,129.41) v1(103.72,117.75) v1(103.74,132.1) v1(104.14,130.83) v1(105.01,156.28) v1(105.01,130.12) v1(105.39,144.34) v1(105.39,141.55) v1(105.39,139.01) v1(105.34,128.09) v1(105.46,134.82) v1(105.59,117.75) v1(105.54,26.92) v1(105.54,25.4) v1(106,116.24) v1(106.05,0.89) v1(106.26,119.91) v1(106.26,117.88) v1(106.4,130.19) v1(106.4,128.32) v1(106.4,127.71) v1(106.4,125.83) v1(106.4,66.17) v1(106.4,64.52) v1(106.43,5.33) v1(106.43,3.81) v1(106.68,109.91) v1(106.68,107.52) v1(106.81,93.76) v1(106.81,26.92) v1(106.81,25.4) v1(107.19,156.34) v1(107.7,5.33) v1(107.7,3.81) v1(108.13,119.91) v1(108.13,117.88) v1(108.39,116.24) v1(108.5,95.45) v1(108.61,127.93) v1(108.59,0.89) v1(108.89,130.09) v1(108.88,113.03) v1(108.88,110.64) v1(108.88,76.51) v1(108.88,74.13) v1(109.73,156.34) v1(109.73,57.78) v1(109.98,68.33) v1(110.25,83.94) v1(110.87,104.73) v1(110.87,102.35) v1(110.87,57.78) v1(111.38,62.23) v1(111.51,156.34) v1(111.51,153.8) v1(111.51,149.99) v1(111.51,147.45) v1(111.51,144.78) v1(111.51,142.24) v1(111.51,139.32) v1(111.51,136.78) v1(111.51,133.99) v1(111.51,131.44) v1(111.51,128.52) v1(111.51,125.98) v1(111.51,123.44) v1(111.51,120.9) v1(111.63,52.07) v1(111.63,49.28) v1(111.63,46.35) v1(111.63,43.18) v1(111.63,38.86) v1(111.63,36.32) v1(111.63,33.15) v1(111.63,30.86) v1(111.63,28.32) v1(111.63,26.29) v1(111.63,23.49) v1(111.63,20.95) v1(111.63,18.16) v1(111.63,15.62) v1(111.63,13.21) v1(111.63,10.67) v1(111.63,8.25) v1(111.63,5.71) v1(111.63,3.68) v1(111.63,1.14) v1(111.92,91.15) v1(111.94,82.25) v1(112.52,62.23) v1(112.65,119.38) v1(113.61,89.46) v1(113.54,52.32) v1(115.19,119.38) v1(115.71,82.18) v1(115.71,79.79) v1(116.59,52.32) v1(116.96,89.51) v1(116.96,87.13) v1(117.22,66.38) v1(117.41,79.07) v1(117.41,76.69) v1(117.45,102.06) v1(117.73,119.38) v1(118.49,66.38) v1(119.14,100.37) v1(119.17,86.35) v1(119.17,83.96) v1(119.25,116.69) v1(119.25,52.32) v1(120.27,119.38) v1(121.65,95.42) v1(121.65,93.03) v1(121.79,52.32) v1(121.92,101.18) v1(121.92,98.79) v1(122.73,59.94) v1(123.57,119.38) v1(124.12,97.78) v1(124.12,95.39) v1(124.21,52.32) v1(126.11,119.38) v1(126.75,52.32) v1(128.91,75.31) v1(128.91,71.5) v1(128.91,70.23) v1(128.91,66.42) v1(128.91,65.15) v1(128.91,61.34) v1(129.03,52.32) v1(129.29,119.38) v1(130.17,74.04) v1(130.17,72.77) v1(130.17,68.96) v1(130.17,67.69) v1(130.17,63.88) v1(130.17,62.61) v1(131.44,74.04) v1(131.44,70.23) v1(131.44,66.42) v1(131.44,62.61) v1(131.57,52.32) v1(131.83,119.38) v1(132.72,75.31) v1(132.72,71.5) v1(132.72,67.69) v1(132.72,63.88) v1(132.72,61.34) v1(133.99,77.85) v1(133.99,74.04) v1(133.99,70.23) v1(133.99,66.42) v1(133.99,62.61) v1(135.25,105.79) v1(135.25,98.17) v1(135.25,94.36) v1(135.25,79.12) v1(135.25,75.31) v1(135.25,71.5) v1(135.25,67.69) v1(135.25,63.88) v1(135.25,61.34) v1(136.53,77.85) v1(136.53,74.04) v1(136.53,70.23) v1(136.53,66.42) v1(136.53,62.61) v1(137.29,52.32) v1(137.67,119.38) v1(137.8,79.12) v1(137.8,75.31) v1(137.8,71.5) v1(137.8,67.69) v1(137.8,63.88) v1(137.8,61.34) v1(139.06,108.33) v1(139.06,80.39) v1(139.06,76.58) v1(139.06,65.15) v1(139.06,62.61) v1(139.83,52.32) v1(140.21,119.38) v1(140.34,105.79) v1(140.34,80.39) v1(140.34,76.58) v1(140.34,75.31) v1(140.34,71.5) v1(140.34,70.23) v1(140.34,66.42) v1(140.34,63.88) v1(140.34,61.34) v1(141.6,108.33) v1(141.6,104.52) v1(141.6,103.25) v1(141.6,99.44) v1(141.6,98.17) v1(141.6,94.36) v1(141.6,93.09) v1(141.6,89.28) v1(141.6,79.12) v1(141.6,77.85) v1(141.6,74.04) v1(141.6,72.77) v1(141.6,68.96) v1(141.6,67.69) v1(141.6,63.88) v1(141.6,62.61) v1(142.75,52.32) v1(142.88,107.06) v1(142.88,105.79) v1(142.88,101.98) v1(142.88,100.71) v1(142.88,96.9) v1(142.88,95.63) v1(142.88,91.82) v1(142.88,90.55) v1(142.88,86.74) v1(142.88,81.66) v1(142.88,80.39) v1(142.88,76.58) v1(142.88,75.31) v1(142.88,71.5) v1(142.88,70.23) v1(142.88,66.42) v1(142.88,65.15) v1(142.88,61.34) v1(143,119.38) v1(144.15,109.6) v1(144.15,108.33) v1(144.15,103.25) v1(144.15,99.44) v1(144.15,98.17) v1(144.15,94.36) v1(144.15,93.09) v1(144.15,89.28) v1(144.15,88.01) v1(144.15,84.2) v1(144.15,82.93) v1(144.15,79.12) v1(144.15,77.85) v1(144.15,74.04) v1(144.15,72.77) v1(144.15,68.96) v1(144.15,67.69) v1(144.15,63.88) v1(144.15,62.61) v1(145.29,52.32) v1(145.41,107.06) v1(145.41,105.79) v1(145.41,101.98) v1(145.41,100.71) v1(145.41,96.9) v1(145.41,95.63) v1(145.41,91.82) v1(145.41,90.55) v1(145.41,86.74) v1(145.41,85.47) v1(145.41,81.66) v1(145.41,80.39) v1(145.41,76.58) v1(145.41,75.31) v1(145.41,71.5) v1(145.41,70.23) v1(145.41,66.42) v1(145.41,65.15) v1(145.41,61.34) v1(145.54,119.38) v1(149.1,119.38) v1(149.22,116.08) v1(149.22,113.03) v1(149.22,109.35) v1(149.22,106.81) v1(149.22,103.12) v1(149.22,100.58) v1(149.22,97.54) v1(149.22,95) v1(149.22,91.57) v1(149.22,88.14) v1(149.22,84.96) v1(149.22,81.79) v1(149.22,78.61) v1(149.22,75.82) v1(149.22,73.03) v1(149.22,70.1) v1(149.22,67.44) v1(149.22,64.9) v1(149.22,61.72) v1(149.22,57.91) v1(149.22,54.99) v1(149.22,52.45) v2(96.1,131.26) v2(97.91,131.26) v3(57.53,63.12) v3(57.53,62.1) v3(57.53,61.09) v3(57.53,60.07) v3(58.04,62.61) v3(58.04,61.59) v3(58.04,60.58) v3(58.55,63.12) v3(58.55,62.1) v3(58.55,61.09) v3(58.55,60.07) v3(59.05,62.61) v3(59.05,61.59) v3(59.05,60.58) v3(59.56,63.12) v3(59.56,62.1) v3(59.56,61.09) v3(59.56,60.07) v3(60.07,62.61) v3(60.07,61.59) v3(60.07,60.58) v3(60.58,63.12) v3(60.58,62.1) v3(60.58,61.09) v3(60.58,60.07) v3(128.91,76.58) v3(131.44,77.85) v3(132.72,79.12) v3(140.34,85.47) v3(142.88,85.47) v3(144.15,104.52) v4(13.6,151.26) v4(13.6,149.05) v4(13.6,146.84) v4(14.49,137.16) v4(14.49,134.95) v4(14.49,132.74) v4(15.11,155.59) v4(15.11,153.94) v4(15.49,152.27) v4(15.49,151.17) v4(15.49,150.06) v4(15.49,148.96) v4(15.49,147.85) v4(15.49,146.75) v4(15.75,139.46) v4(15.88,141.24) v4(16.26,138.05) v4(16.26,136.94) v4(16.26,135.84) v4(16.26,134.73) v4(16.26,133.63) v4(16.26,132.52) v4(16.6,152.27) v4(16.6,151.17) v4(16.6,150.06) v4(16.6,148.96) v4(16.6,147.85) v4(16.6,146.75) v4(17.32,155.59) v4(17.32,153.94) v4(17.36,138.05) v4(17.36,136.94) v4(17.36,135.84) v4(17.36,134.73) v4(17.36,133.63) v4(17.36,132.52) v4(17.7,152.27) v4(17.7,151.17) v4(17.7,150.06) v4(17.7,148.96) v4(17.7,147.85) v4(17.7,146.75) v4(17.96,139.46) v4(18.08,141.24) v4(18.47,138.05) v4(18.47,136.94) v4(18.47,135.84) v4(18.47,134.73) v4(18.47,133.63) v4(18.47,132.52) v4(18.81,152.27) v4(18.81,151.17) v4(18.81,150.06) v4(18.81,148.96) v4(18.81,147.85) v4(18.81,146.75) v4(19.53,155.59) v4(19.53,153.94) v4(19.57,138.05) v4(19.57,136.94) v4(19.57,135.84) v4(19.57,134.73) v4(19.57,133.63) v4(19.57,132.52) v4(20.17,139.46) v4(20.29,141.24) v4(20.59,151.13) v4(20.59,148.92) v4(20.59,146.71) v4(20.97,137.16) v4(20.97,134.95) v4(20.97,132.74) v4(21.6,115.31) v4(21.6,76.21) v4(21.7,117.5) v4(21.7,74.01) v4(21.9,114.1) v4(21.9,77.41) v4(22.8,118.4) v4(22.8,73.11) v4(24.8,118.4) v4(24.8,73.11) v4(25.7,114.1) v4(25.9,117.5) v4(25.9,74.01) v4(26,115.31) v4(26,76.21) v4(37.85,115.31) v4(37.85,76.21) v4(37.95,117.5) v4(37.95,74.01) v4(38.15,114.1) v4(38.15,77.41) v4(39.05,118.4) v4(39.05,73.11) v4(39.88,21.21) v4(39.88,18.67) v4(39.88,5.08) v4(39.88,2.54) v4(41.05,118.4) v4(41.05,73.11) v4(41.95,114.1) v4(41.95,77.41) v4(42.15,117.5) v4(42.15,74.01) v4(42.25,115.31) v4(42.25,76.21) v4(45.34,5.59) v4(45.34,3.05) v4(45.47,21.72) v4(45.47,19.18) v4(45.85,15.49) v4(46.1,31.62) v4(46.61,4.32) v4(46.74,20.45) v4(46.88,131.75) v4(46.88,129.75) v4(47.62,27.05) v4(47.62,24.51) v4(47.62,11.56) v4(47.62,9.02) v4(47.78,132.85) v4(47.78,128.65) v4(47.88,5.59) v4(47.88,3.05) v4(48.01,21.72) v4(48.01,19.18) v4(48.39,15.49) v4(48.64,31.62) v4(49.66,29.34) v4(49.66,28.07) v4(49.66,26.8) v4(49.66,25.53) v4(49.66,24.26) v4(49.66,22.99) v4(49.66,21.72) v4(49.66,13.34) v4(49.66,12.06) v4(49.66,10.79) v4(49.66,9.53) v4(49.66,8.25) v4(49.66,6.98) v4(49.66,5.71) v4(49.98,132.95) v4(49.98,128.55) v4(50.93,29.34) v4(50.93,28.07) v4(50.93,26.8) v4(50.93,25.53) v4(50.93,24.26) v4(50.93,22.99) v4(50.93,21.72) v4(50.93,13.34) v4(50.93,12.06) v4(50.93,10.79) v4(50.93,9.53) v4(50.93,8.25) v4(50.93,6.98) v4(50.93,5.71) v4(51.05,2.79) v4(51.18,132.65) v4(51.18,128.85) v4(52.2,29.34) v4(52.2,28.07) v4(52.2,26.8) v4(52.2,25.53) v4(52.2,24.26) v4(52.2,22.99) v4(52.2,21.72) v4(52.2,13.34) v4(52.2,12.06) v4(52.2,10.79) v4(52.2,9.53) v4(52.2,8.25) v4(52.2,6.98) v4(52.2,5.71) v4(54.61,15.62) v4(54.61,13.08) v4(54.74,21.08) v4(54.74,18.54) v4(54.74,10.67) v4(54.74,8) v4(54.74,5.21) v4(54.74,2.67) v4(54.86,31.75) v4(54.86,29.21) v4(82.8,22.99) v4(84.18,10.69) v4(84.18,8.13) v4(84.18,5.59) v4(84.18,3.05) v4(84.43,31.39) v4(84.43,28.83) v4(84.43,26.29) v4(84.43,23.75) v4(86.08,31.78) v4(86.08,30.48) v4(86.08,29.21) v4(86.08,27.94) v4(86.08,26.67) v4(86.08,25.4) v4(86.08,24.13) v4(86.08,10.57) v4(86.08,9.27) v4(86.08,8) v4(86.08,6.73) v4(86.08,5.46) v4(86.08,4.19) v4(86.08,2.92) v4(86.74,22.73) v4(87.38,31.78) v4(87.38,30.48) v4(87.38,29.21) v4(87.38,27.94) v4(87.38,26.67) v4(87.38,25.4) v4(87.38,24.13) v4(87.38,10.57) v4(87.38,9.27) v4(87.38,8) v4(87.38,6.73) v4(87.38,5.46) v4(87.38,4.19) v4(87.38,2.92) v4(88.65,31.78) v4(88.65,30.48) v4(88.65,29.21) v4(88.65,27.94) v4(88.65,26.67) v4(88.65,25.4) v4(88.65,24.13) v4(88.65,10.57) v4(88.65,9.27) v4(88.65,8) v4(88.65,6.73) v4(88.65,5.46) v4(88.65,4.19) v4(88.65,2.92) v4(89.92,31.78) v4(89.92,30.48) v4(89.92,29.21) v4(89.92,27.94) v4(89.92,26.67) v4(89.92,25.4) v4(89.92,24.13) v4(89.92,10.57) v4(89.92,9.27) v4(89.92,8) v4(89.92,6.73) v4(89.92,5.46) v4(89.92,4.19) v4(89.92,2.92) v4(90.81,22.86) v4(91.19,31.78) v4(91.19,30.48) v4(91.19,29.21) v4(91.19,27.94) v4(91.19,26.67) v4(91.19,25.4) v4(91.19,24.13) v4(91.19,10.57) v4(91.19,9.27) v4(91.19,8) v4(91.19,6.73) v4(91.19,5.46) v4(91.19,4.19) v4(91.19,2.92) v4(92.3,11.07) v4(92.3,8.51) v4(92.3,5.97) v4(92.3,3.43) v4(92.56,31.78) v4(92.56,29.21) v4(92.56,26.67) v4(92.56,24.13) v5(60.53,137.84) v5(61.55,139.87) v5(61.55,138.86) v5(61.55,137.84) v5(62.56,140.89) v5(62.56,138.86)
